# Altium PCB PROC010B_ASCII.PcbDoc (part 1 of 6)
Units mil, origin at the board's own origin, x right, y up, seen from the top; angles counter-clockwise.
Board outline 3180 x 2565 mil, 6 copper layers (TOP, L2, L3, L4, L5, BOTTOM), stack 55.54 mil thick; 362 components, 264 nets, 1248 pads, 1144 vias.
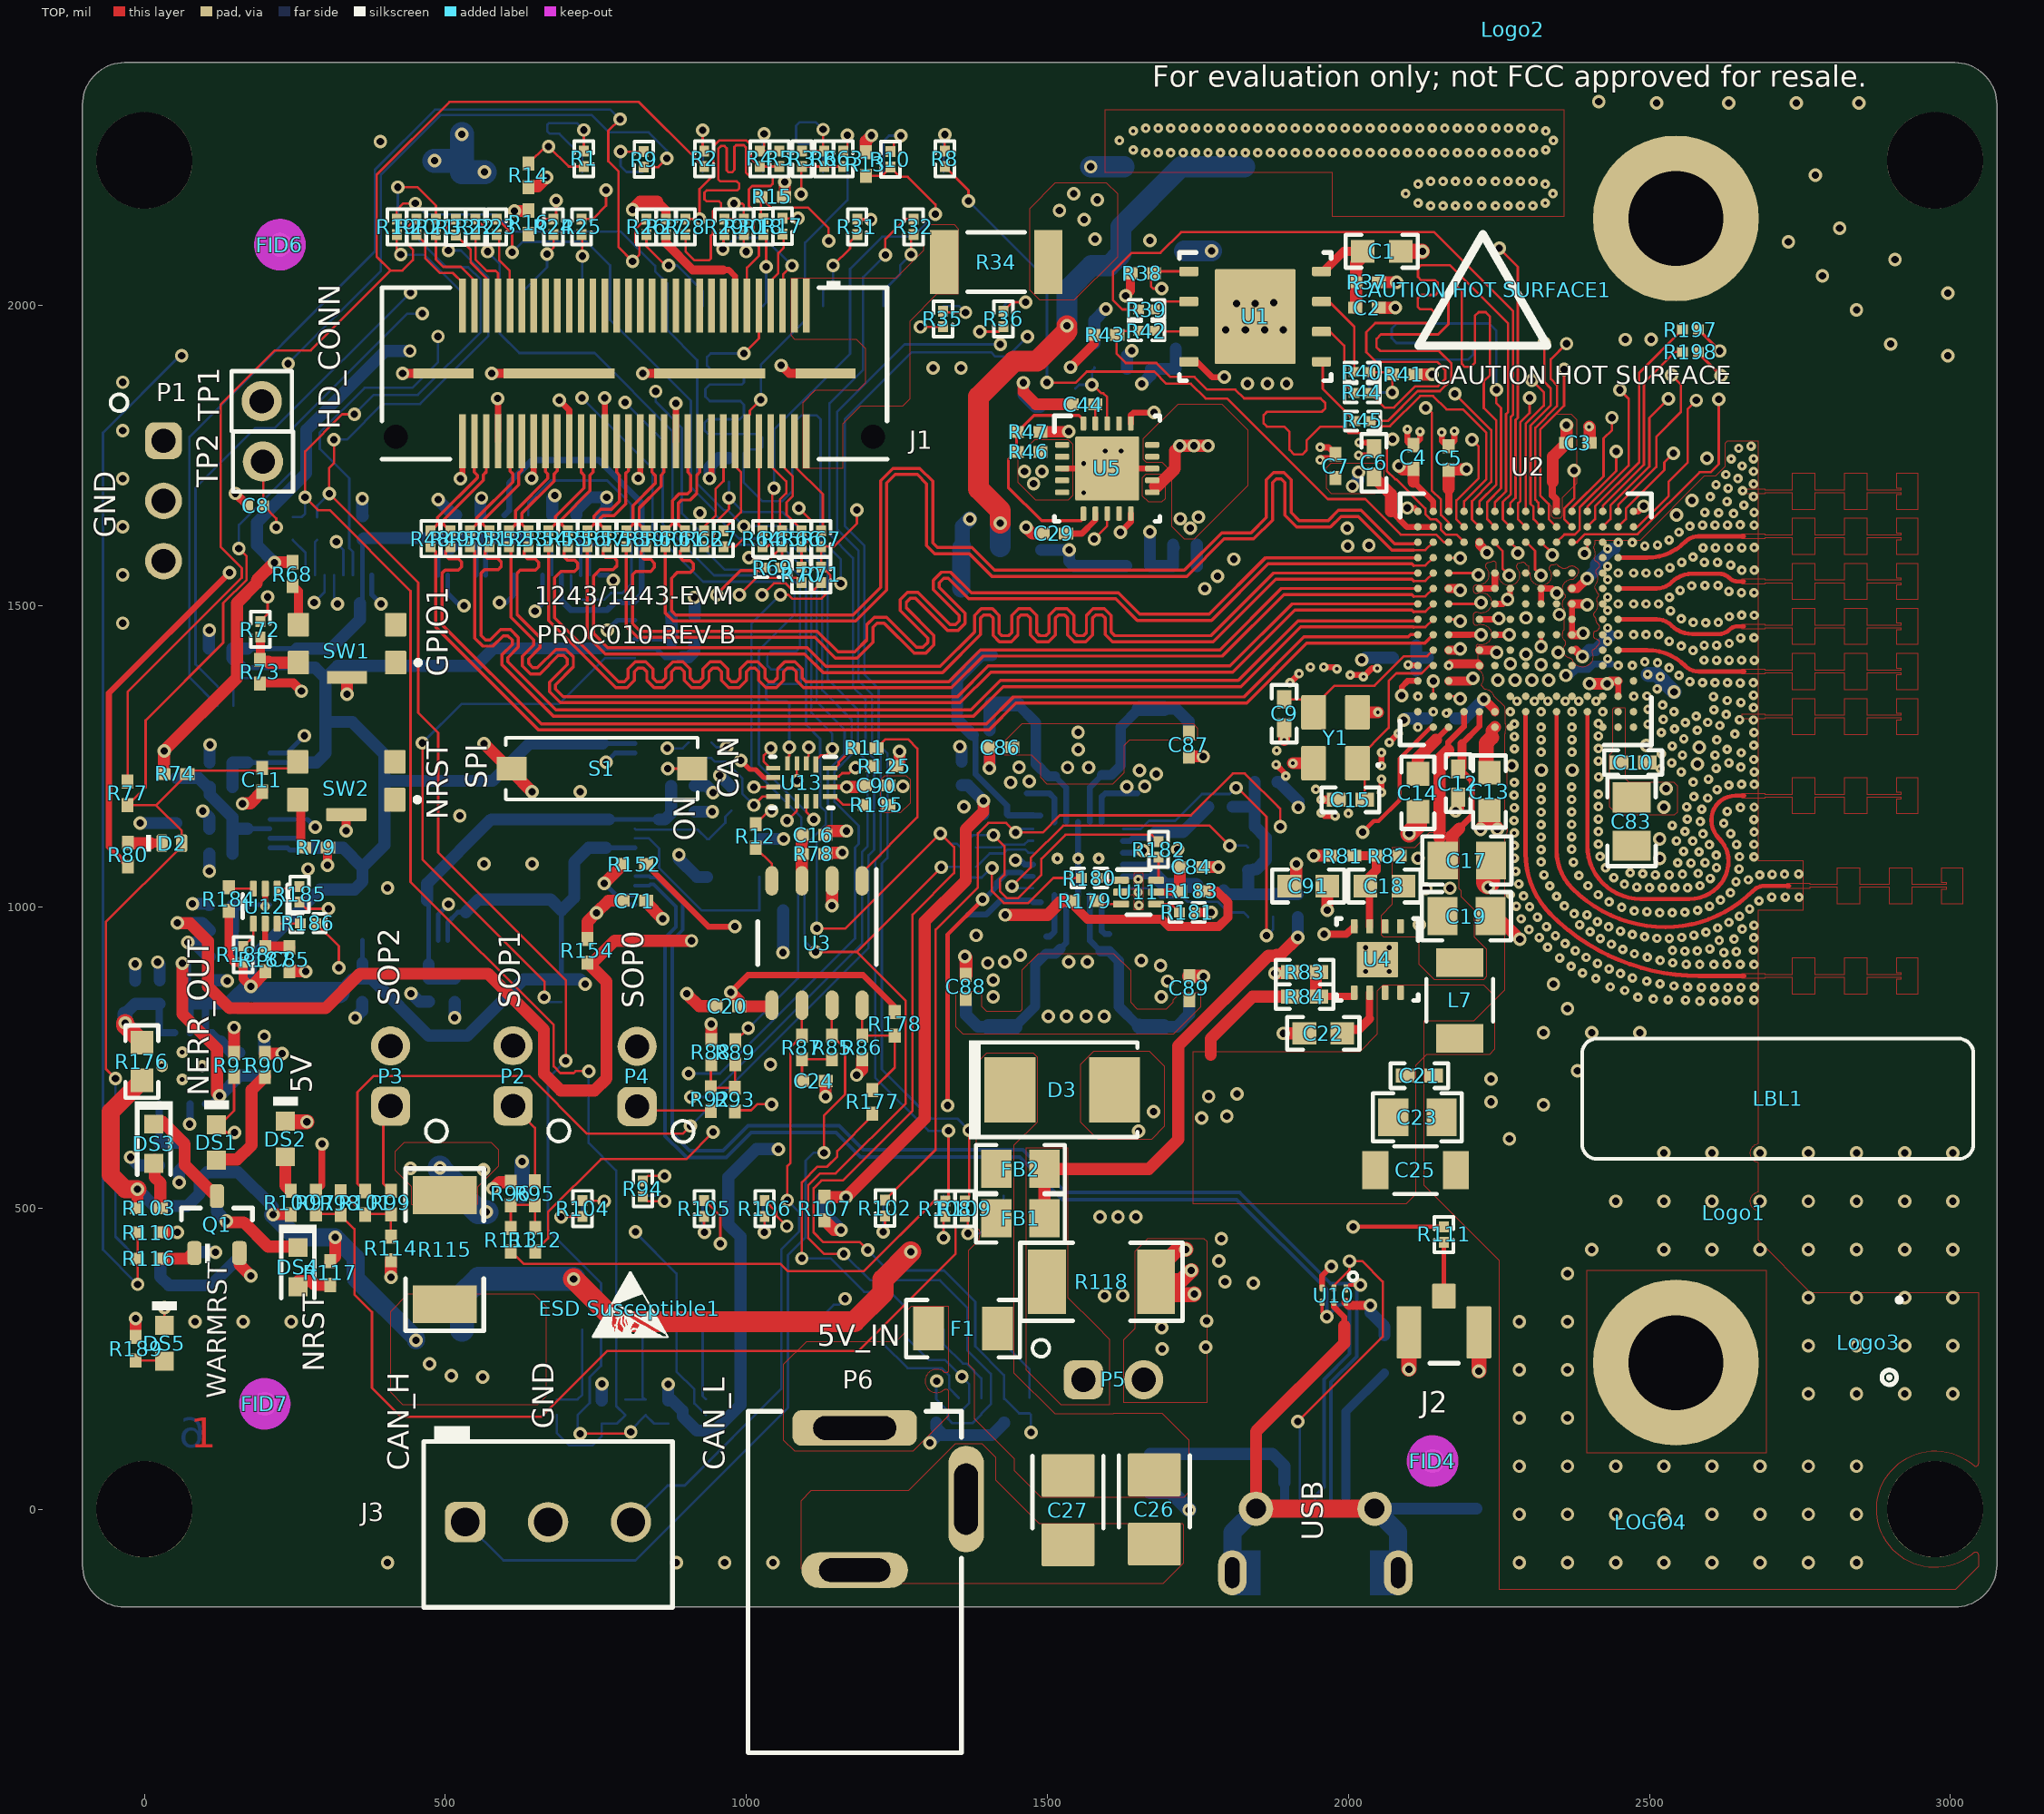
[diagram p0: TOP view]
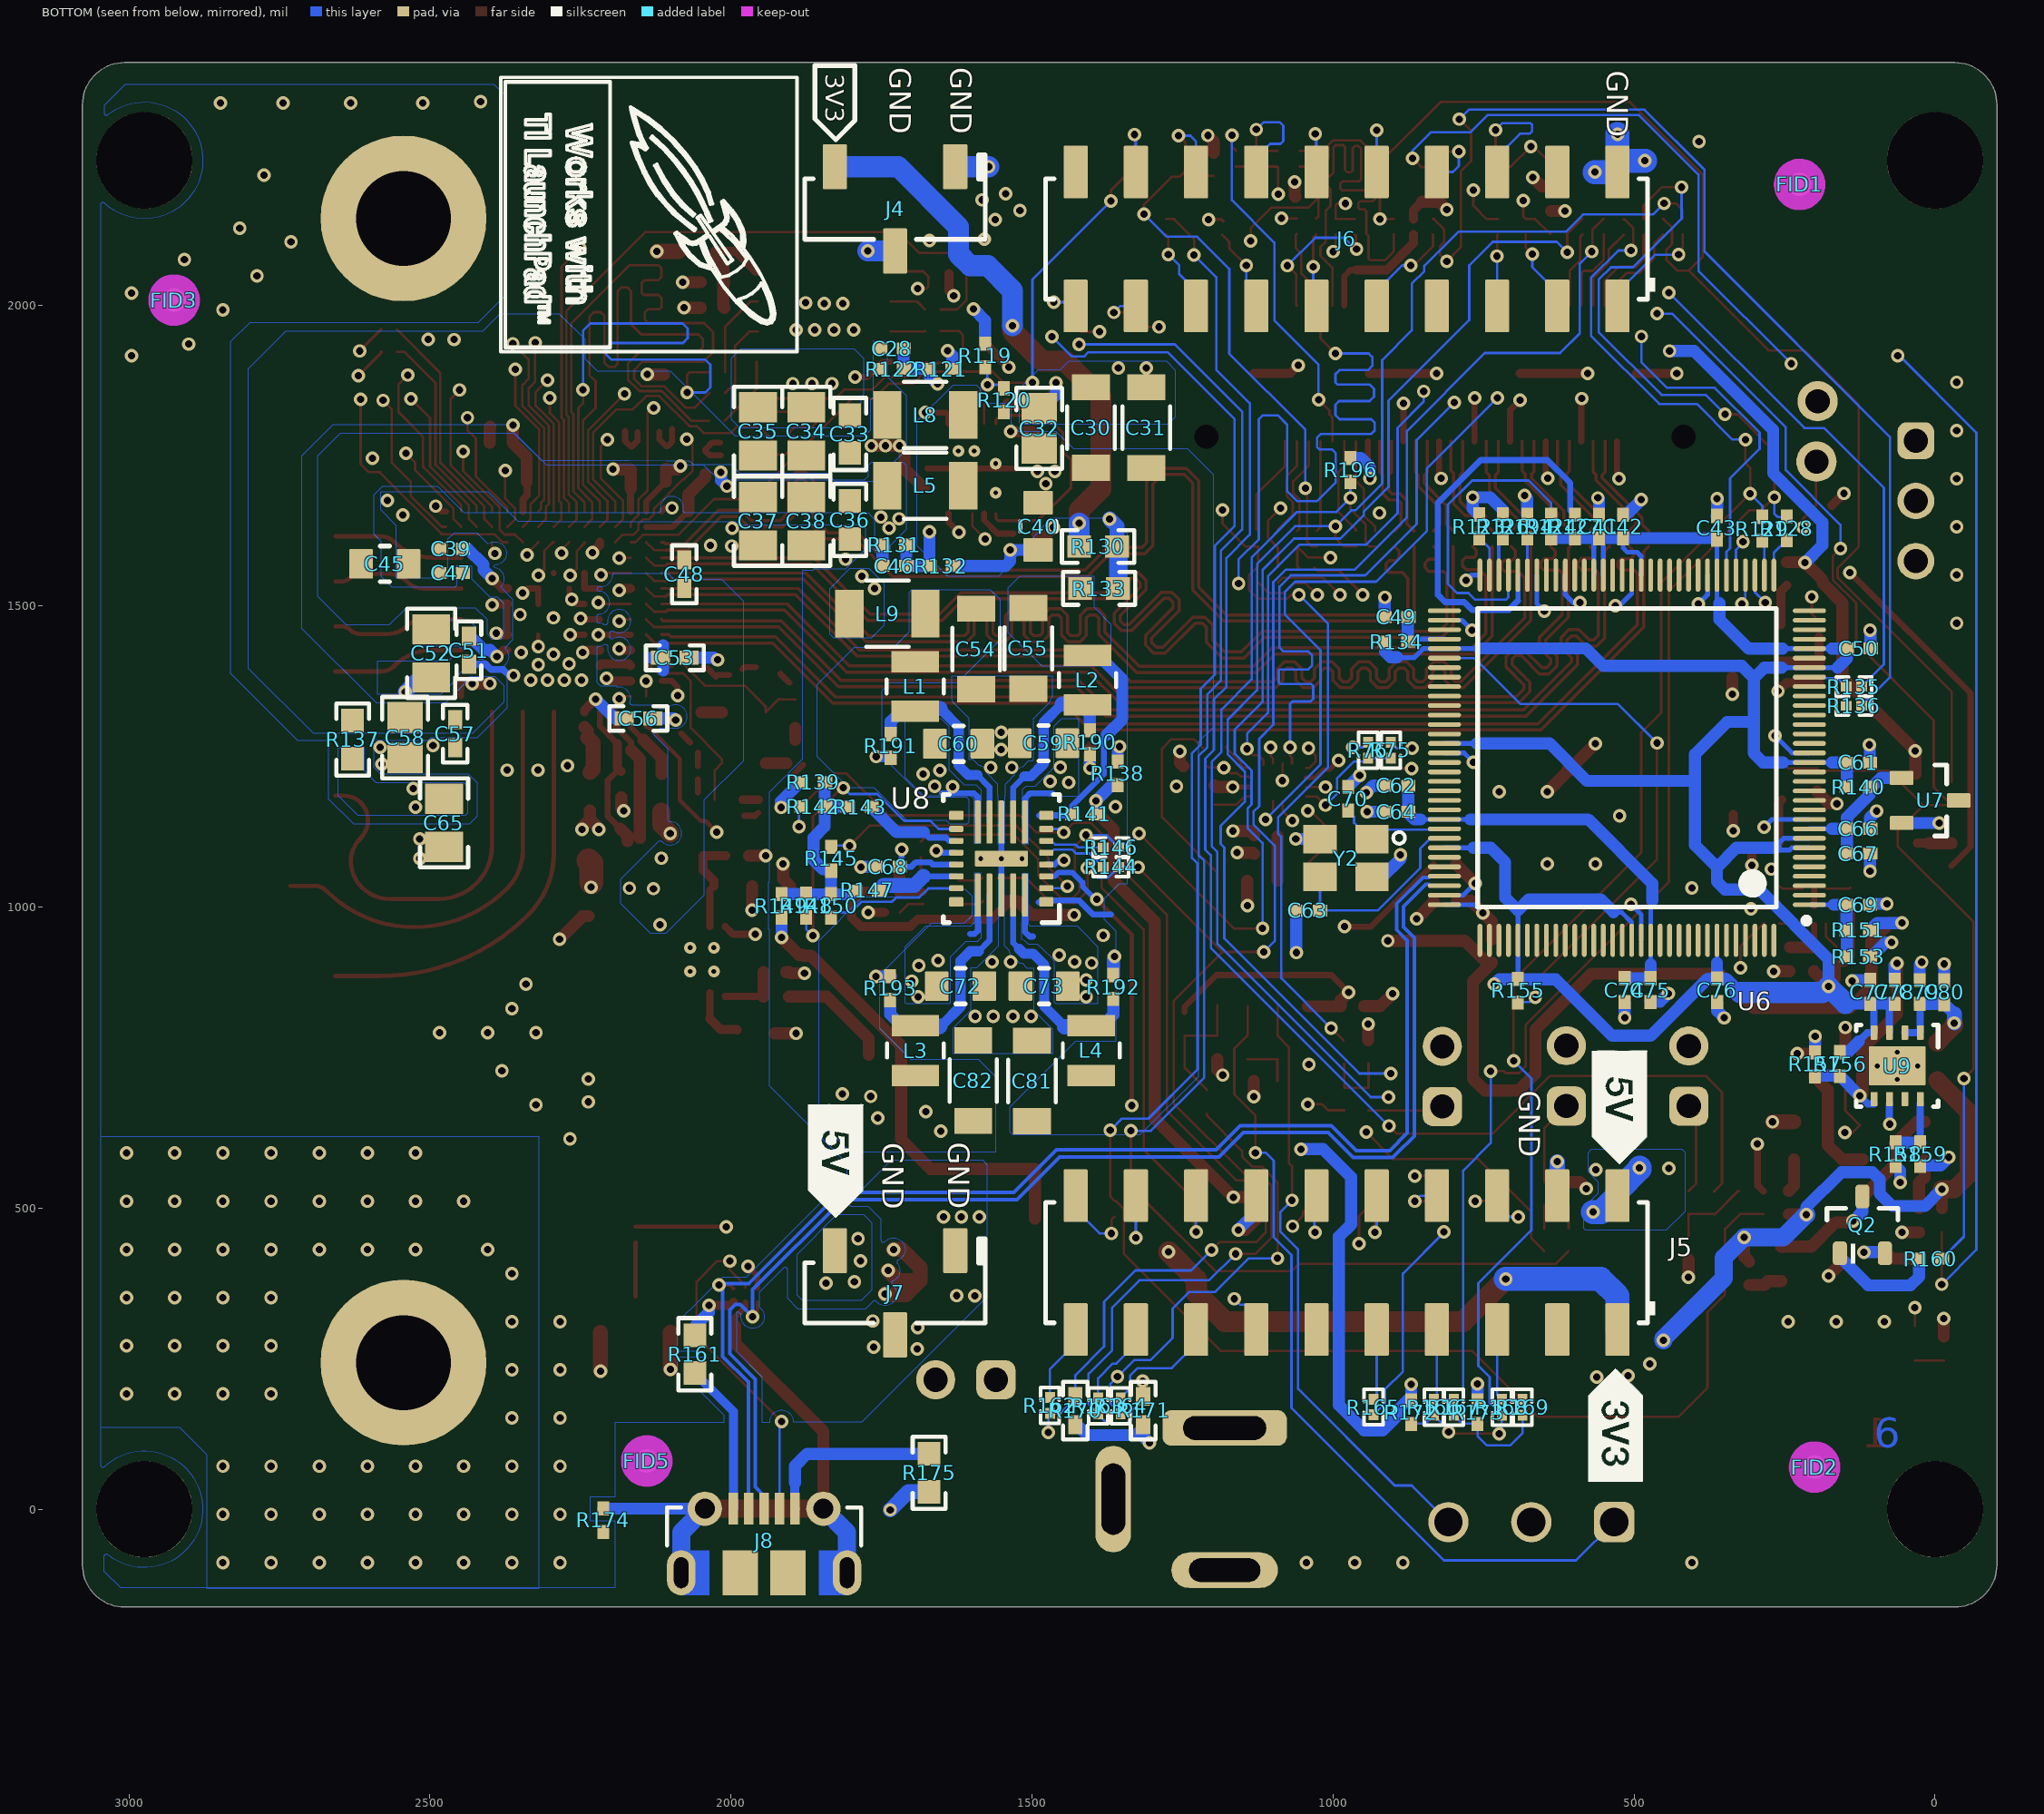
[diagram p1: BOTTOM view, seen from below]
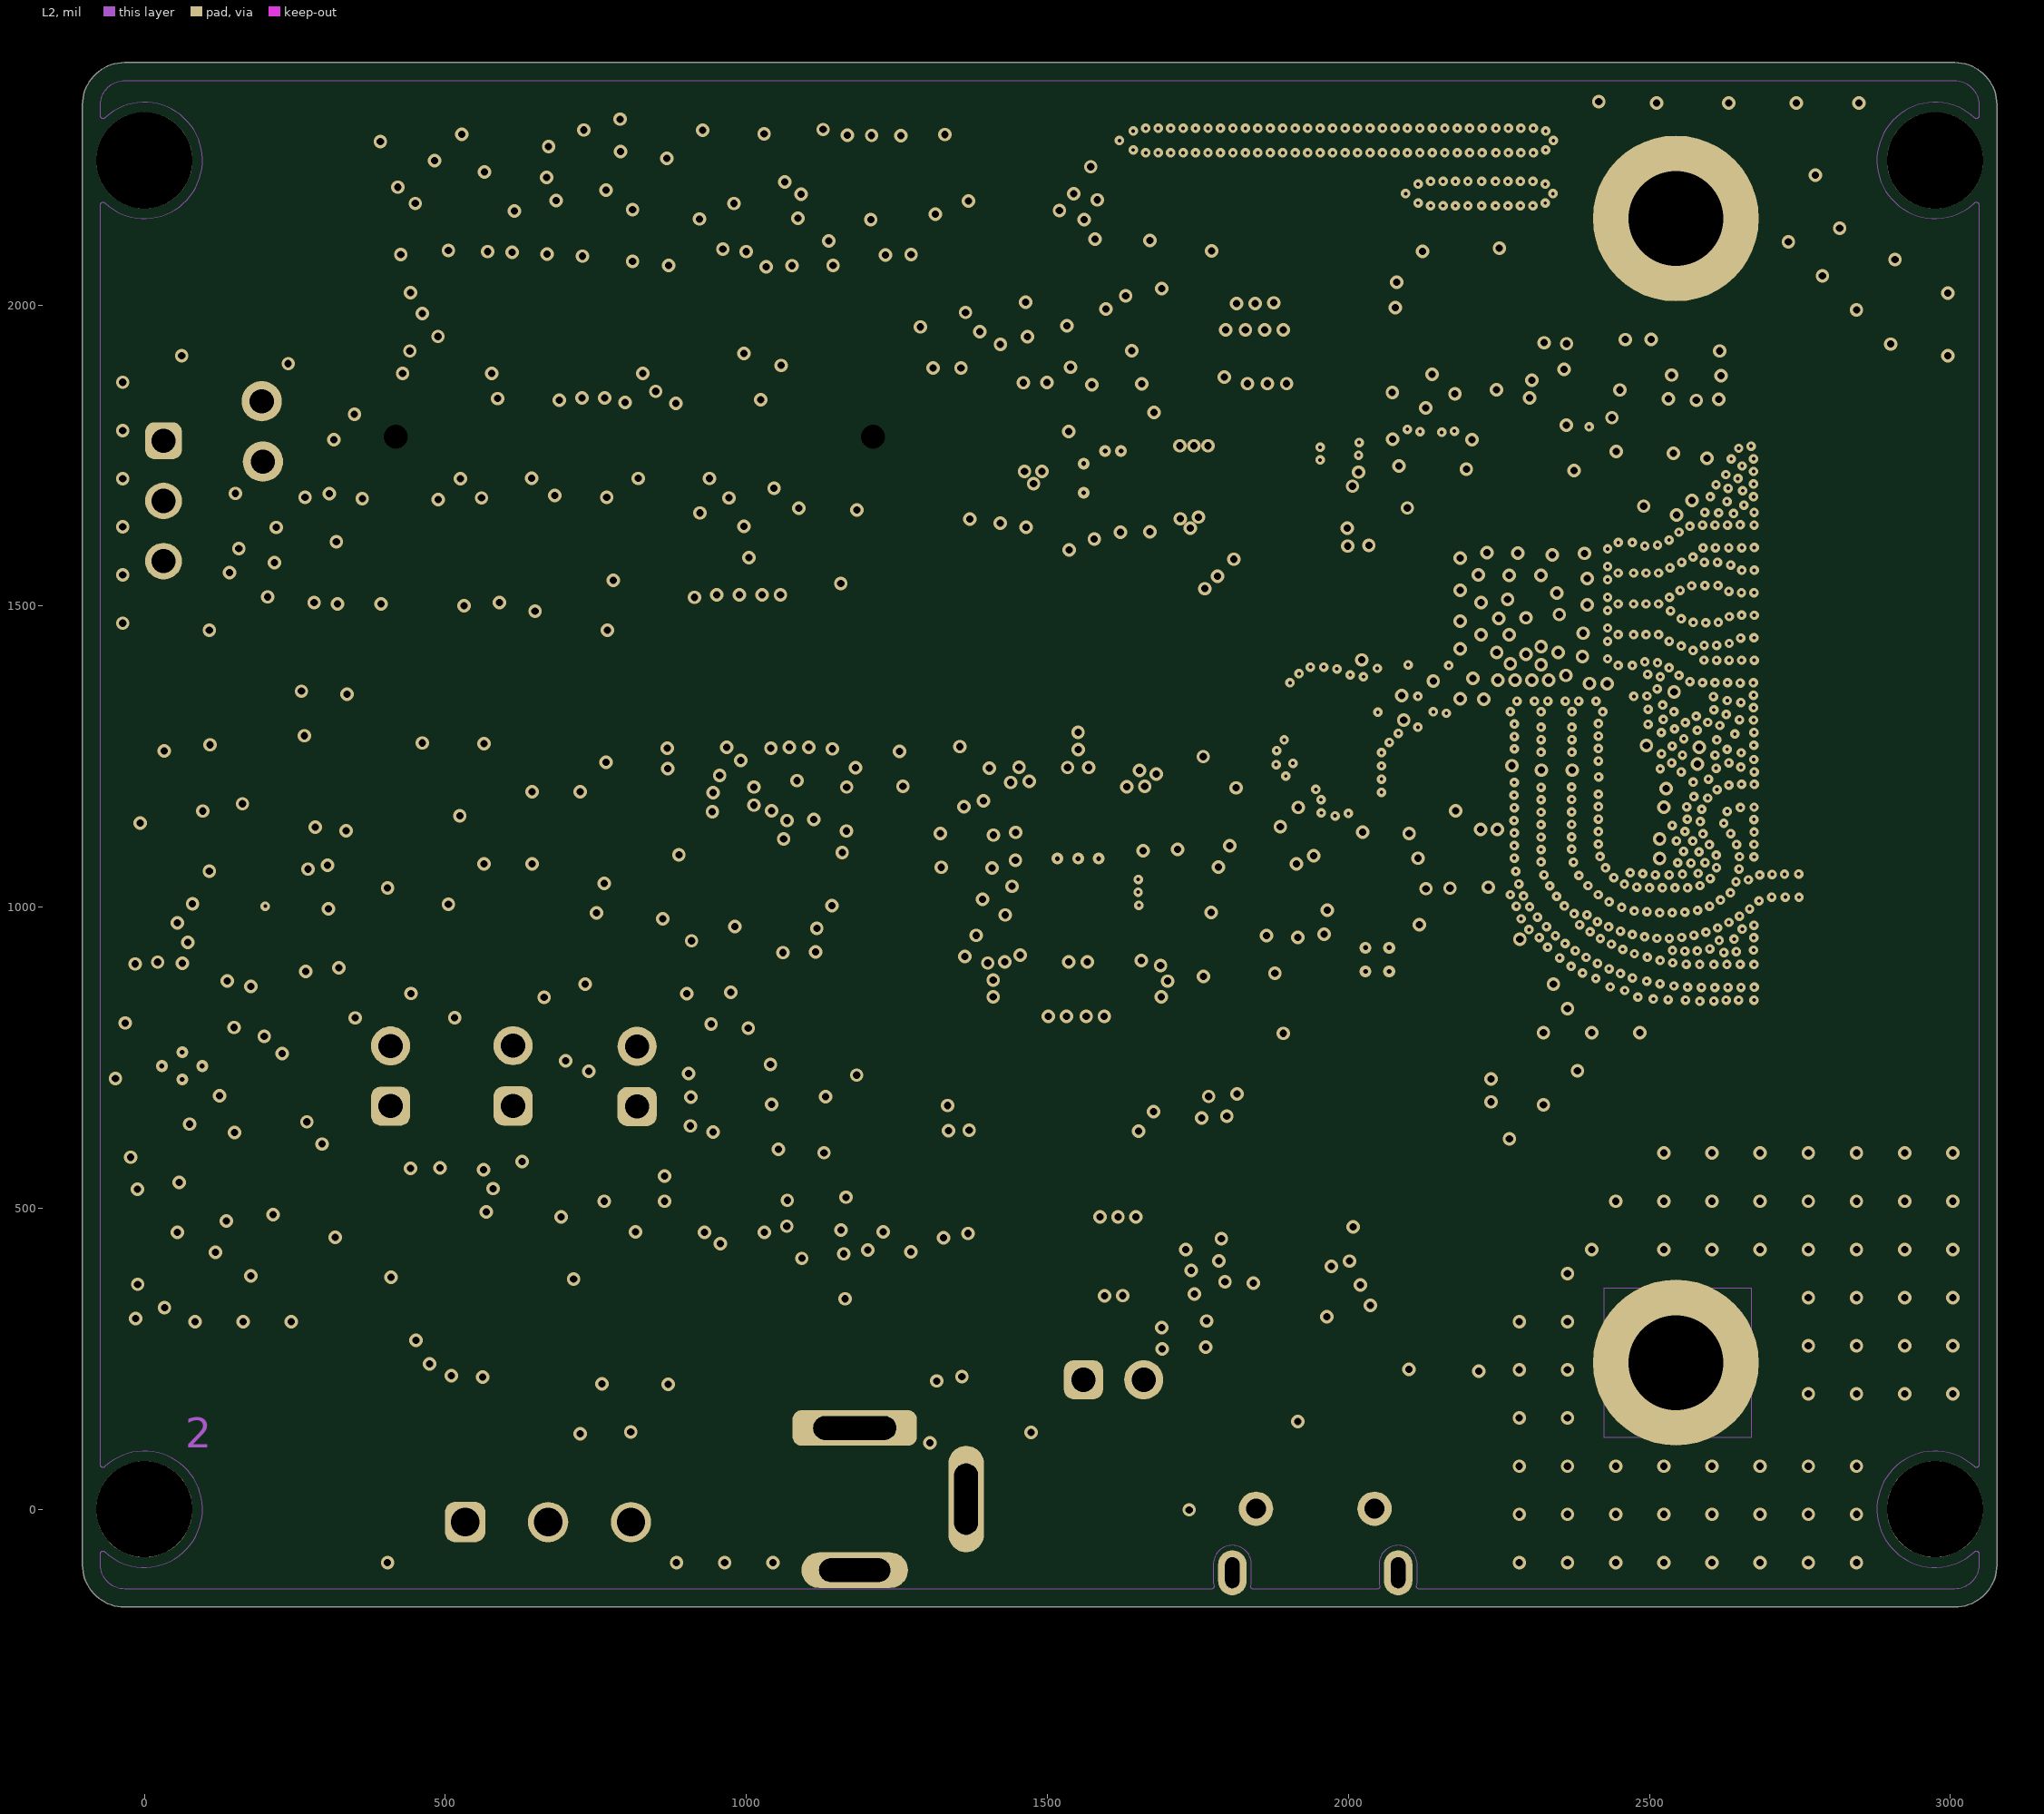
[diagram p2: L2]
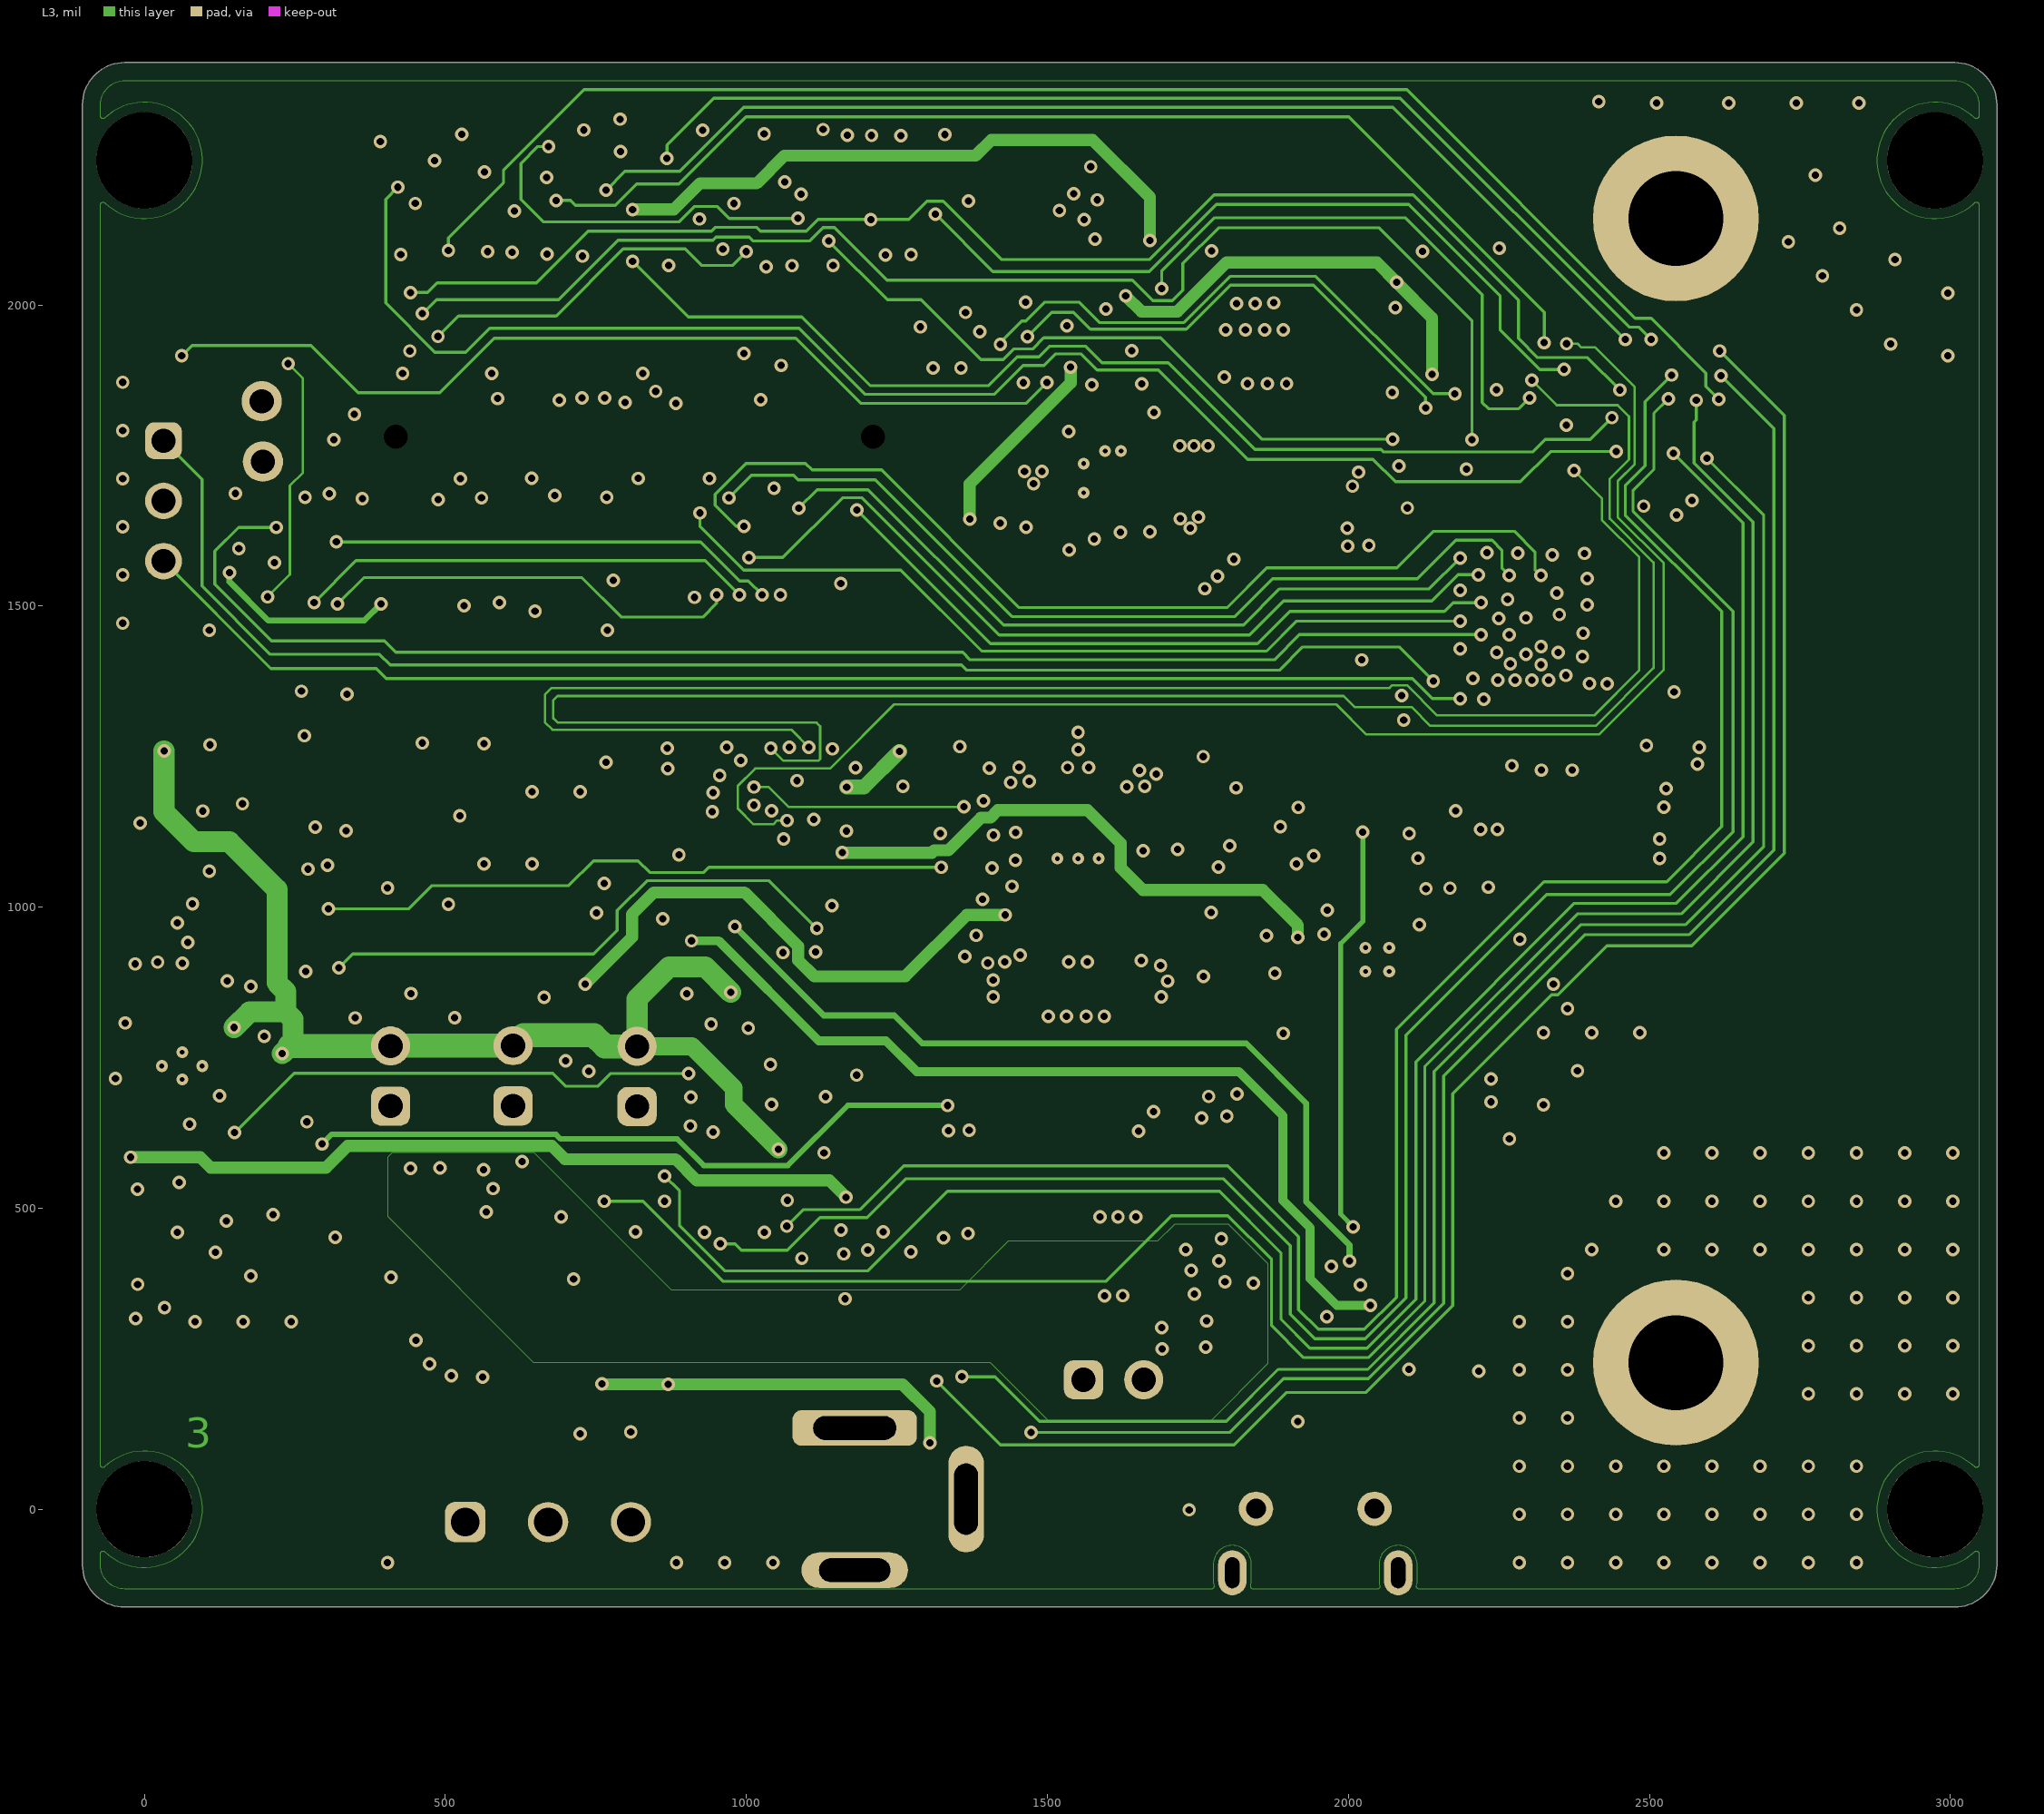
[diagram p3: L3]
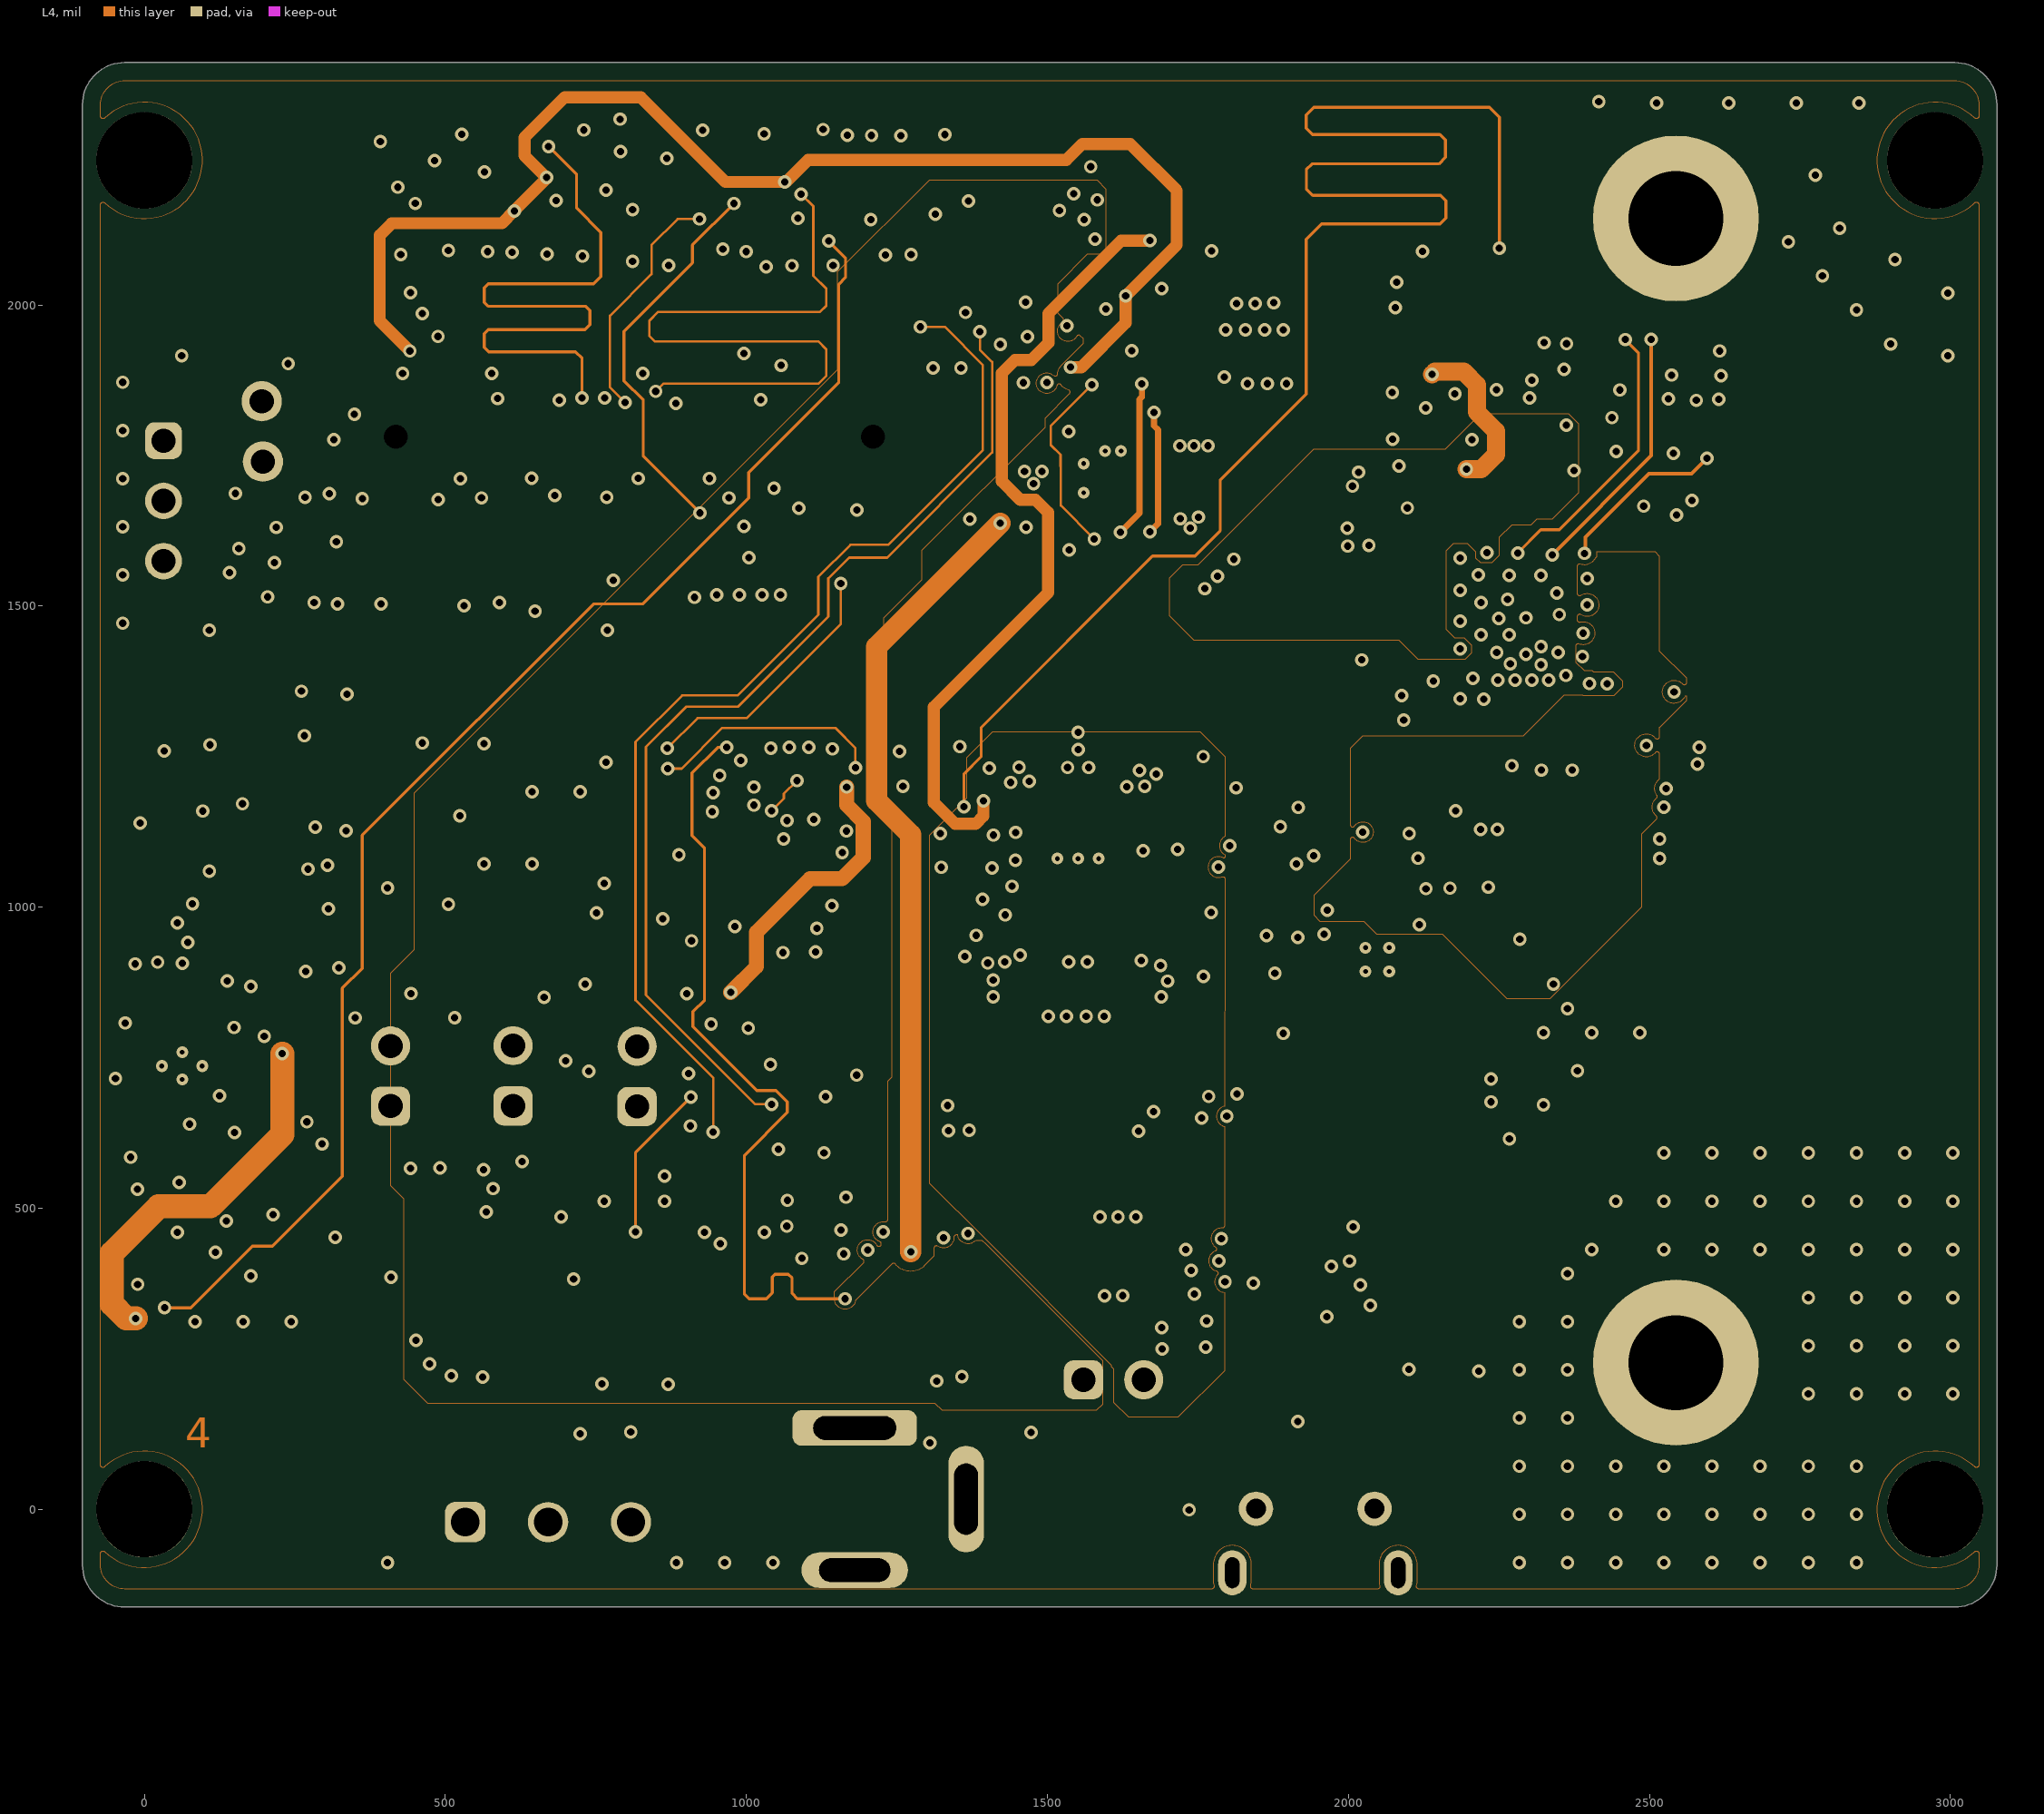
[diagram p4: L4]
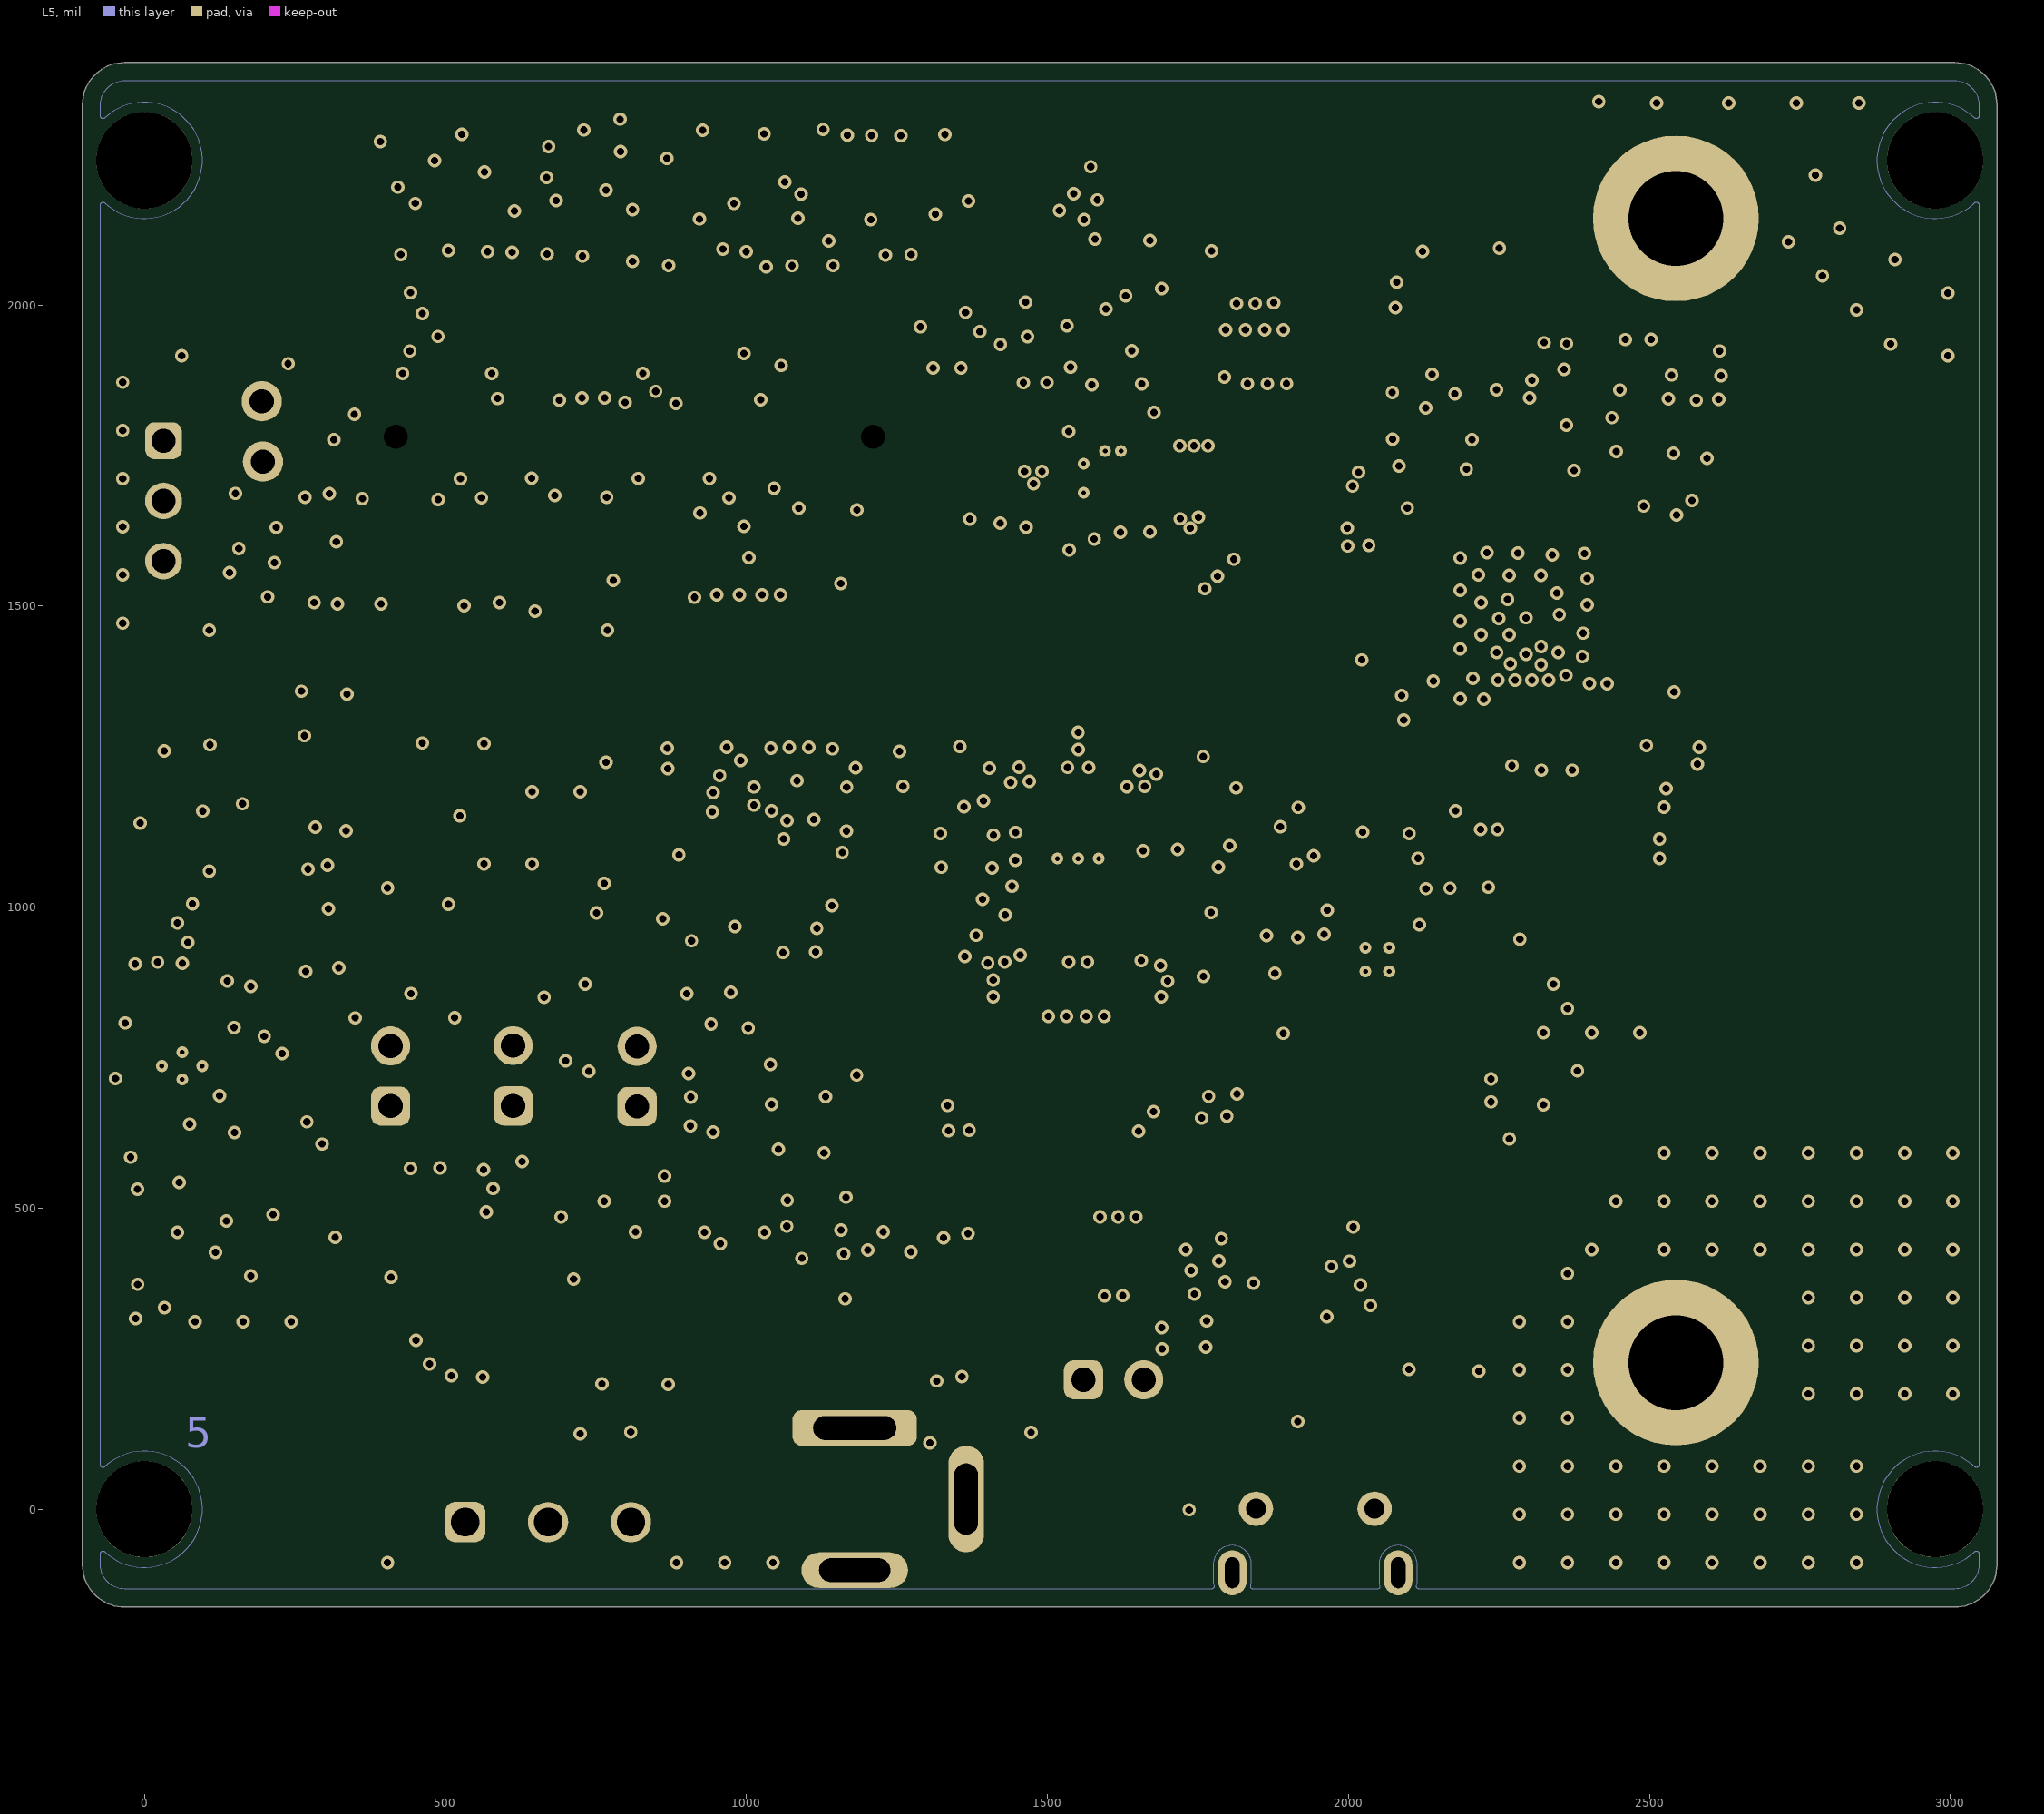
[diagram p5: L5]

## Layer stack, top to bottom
Top Solder: solder mask 0.8, Solder Resist, Dk 3.5
TOP: signal copper 1.6
Dielectric 1: core 4, RO4835 LOPRO, Dk 3.66
L2: signal copper 1.2
Dielectric2: core 2.85, FR4 370HR, Dk 3.9
Dielectric 3: dielectric 2.85, FR4 370HR, Dk 3.9
L3: signal copper 1.2
Dielectric4: core 28, FR4 370HR, Dk 4.36
L4: signal copper 1.2
Dielectric5: core 2.92, FR4 370HR, Dk 3.9
Dielectric 6: dielectric 2.92, FR4 370HR, Dk 3.9
L5: signal copper 1.2
Dielectric7: core 4, FR4 370HR, Dk 4.26
BOTTOM: signal copper 1.6
Bottom Solder: solder mask 0.8, Solder Resist, Dk 3.5

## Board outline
-32.75,-162.5 cw(c-32.75,-92.5) -102.75,-92.5 -102.75,2332.5 cw(c-32.75,2332.5) -32.75,2402.5 3007.25,2402.5 cw(c3007.25,2332.5) 3077.25,2332.5 3077.25,-92.5 cw(c3007.25,-92.5) 3007.25,-162.5

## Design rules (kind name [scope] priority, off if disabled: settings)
AssemblyTestPointUsage [All] p0: scope1count=1 scope1_0_kind=Board scope1_0_value=Board scope2count=1 scope2_0_kind=Board scope2_0_value=Board commentlength=0
AssemblyTestpoint [All] p0: scope1count=1 scope1_0_kind=Board scope1_0_value=Board scope2count=1 scope2_0_kind=Board scope2_0_value=Board commentlength=0
Clearance Clearance_RF [All] p0 off: scope1count=1 scope1_0_kind=Board scope1_0_value=Board scope2count=1 scope2_0_kind=Board scope2_0_value=Board commentlength=45 gap=6.73 // Protel DXP Scope 2 Expression Was: inpoly
Clearance Clearance_L34 [All] p0 off: scope1count=1 scope1_0_kind=Board scope1_0_value=Board scope2count=1 scope2_0_kind=Board scope2_0_value=Board commentlength=60 gap=15 // Protel DXP Scope 1 Expression Was: InLayerClass('L3_L4')
Clearance Clearance_PMIC [All] p0 off: scope1count=1 scope1_0_kind=Board scope1_0_value=Board scope2count=1 scope2_0_kind=Board scope2_0_value=Board commentlength=70 gap=5 // Protel DXP Scope 1 Expression Was: WithinRoom('Copper to PMIC IC')
Clearance Clearance_BTM [All] p0: scope1count=1 scope1_0_kind=Layer scope1_0_value=BOTTOM scope2count=1 scope2_0_kind=Board scope2_0_value=Board commentlength=0 gap=15
Clearance Clearance_L25 [All] p0 off: scope1count=1 scope1_0_kind=Board scope1_0_value=Board scope2count=1 scope2_0_kind=Board scope2_0_value=Board commentlength=60 gap=15 // Protel DXP Scope 1 Expression Was: InLayerClass('L2_L5')
Clearance RX_TX_L34 [All] p0 off: scope1count=1 scope1_0_kind=Board scope1_0_value=Board scope2count=1 scope2_0_kind=NetClass scope2_0_value=RX_TX commentlength=60 gap=10 // Protel DXP Scope 1 Expression Was: InLayerClass('L3_L4')
Clearance COPLANNER [All] p0 off: scope1count=1 scope1_0_kind=Board scope1_0_value=Board scope2count=1 scope2_0_kind=Board scope2_0_value=Board commentlength=81 gap=3 // Protel DXP Scope 1 Expression Was: WithinRoom('COUPLE') and not OnLayer('L4')
Clearance Clearance_1 [All] p0 off: scope1count=1 scope1_0_kind=Board scope1_0_value=Board scope2count=1 scope2_0_kind=Board scope2_0_value=Board commentlength=69 gap=6.71 // Protel DXP Scope 1 Expression Was: WithinRoom('DUT') OR InPolygon
Clearance Clearance_TOP [All] p0: scope1count=1 scope1_0_kind=Layer scope1_0_value=TOP scope2count=1 scope2_0_kind=Board scope2_0_value=Board commentlength=0 gap=10
Clearance RX_TX_L25 [All] p0 off: scope1count=1 scope1_0_kind=Board scope1_0_value=Board scope2count=1 scope2_0_kind=NetClass scope2_0_value=RX_TX commentlength=60 gap=10 // Protel DXP Scope 1 Expression Was: InLayerClass('L2_L5')
Clearance RX_TX_TOP [All] p0: scope1count=1 scope1_0_kind=Layer scope1_0_value=TOP scope2count=1 scope2_0_kind=NetClass scope2_0_value=RX_TX commentlength=0 gap=10
Clearance same_net_cl_inner [All] p0 off: scope1count=1 scope1_0_kind=Board scope1_0_value=Board scope2count=1 scope2_0_kind=Board scope2_0_value=Board commentlength=61 gap=10 // Protel DXP Scope 1 Expression Was: InLayerClass('layers')
Clearance Clearance_RF [InNetClass('RF') and not ispad vs inpoly] p1: gap=6.73 ignorepadtopadclearanceinfootprint=FALSE
Clearance Clearance_L34 [InLayerClass('L3_L4')] p2: gap=15 ignorepadtopadclearanceinfootprint=FALSE except(0: Arc-Hole Track-Hole SMDPad-Hole THPad-Hole Via-Hole Fill-Hole Poly-Hole Region-Hole Text-Hole; 5: Arc-Track Arc-SMDPad Track-Track Track-SMDPad; 5.9: Via-Via; 6: Arc-Arc Arc-THPad Arc-Via Track-THPad Track-Via SMDPad-SMDPad SMDPad-THPad SMDPad-Via SMDPad-Fill SMDPad-Poly THPad-THPad THPad-Via Via-Fill Via-Poly; 10: THPad-Fill THPad-Poly)
Clearance Clearance_PMIC [WithinRoom('Copper to PMIC IC')] p3: gap=5 ignorepadtopadclearanceinfootprint=FALSE except(0: Arc-Hole Track-Hole SMDPad-Hole THPad-Hole Via-Hole Fill-Hole Poly-Hole Region-Hole Text-Hole; 4: Arc-Track Track-Track; 4.5: Track-Via SMDPad-SMDPad)
Clearance Clearance_BTM [OnLayer('BOTTOM')] p4: gap=15 ignorepadtopadclearanceinfootprint=FALSE except(0: Arc-SMDPad Arc-Hole Track-Hole SMDPad-Hole THPad-Hole Via-Hole Fill-Hole Poly-Hole Region-Hole Text-Hole; 4: Track-SMDPad; 4.5: Arc-Via Track-Via; 5: Arc-Arc Arc-Track Track-Track SMDPad-Via; 6: Arc-THPad Track-THPad SMDPad-SMDPad SMDPad-THPad THPad-THPad THPad-Via; 8: Arc-Fill Arc-Poly Track-Fill Track-Poly Via-Fill Via-Poly; 9: SMDPad-Fill SMDPad-Poly THPad-Fill THPad-Poly; 16.6: Via-Via)
Clearance Clearance_L25 [InLayerClass('L2_L5')] p5: gap=15 ignorepadtopadclearanceinfootprint=FALSE except(0: Arc-Hole Track-Hole SMDPad-Hole THPad-Hole Via-Hole Fill-Hole Poly-Hole Region-Hole Text-Hole; 5: Arc-Track Arc-SMDPad Track-Track Track-SMDPad; 6: Arc-Arc Arc-THPad Arc-Via Track-THPad Track-Via SMDPad-SMDPad SMDPad-THPad SMDPad-Via SMDPad-Fill SMDPad-Poly THPad-THPad THPad-Via Via-Via Via-Fill Via-Poly; 10: THPad-Fill THPad-Poly)
Clearance RX_TX_L34 [InLayerClass('L3_L4') vs InNetClass('RX_TX')] p6: gap=10 ignorepadtopadclearanceinfootprint=FALSE except(0: Arc-Hole Track-Hole SMDPad-Hole THPad-Hole Via-Hole Fill-Hole Poly-Hole Region-Hole Text-Hole; 4.86: Via-Via; 5: Arc-SMDPad Track-SMDPad; 6: Arc-Arc Arc-Track Arc-THPad Arc-Via Track-Track Track-THPad Track-Via SMDPad-SMDPad SMDPad-THPad SMDPad-Via SMDPad-Fill SMDPad-Poly THPad-THPad THPad-Via Via-Fill Via-Poly; 15: Arc-Fill Arc-Poly Track-Poly Fill-Fill Fill-Poly Poly-Poly; 16: Track-Fill)
Clearance COPLANNER [WithinRoom('COUPLE') and not OnLayer('L4')] p7: gap=3 ignorepadtopadclearanceinfootprint=FALSE except(0: Arc-Hole Track-Hole SMDPad-Hole THPad-Hole Via-Hole Fill-Hole Poly-Hole Region-Hole Text-Hole)
Clearance Clearance_1 [WithinRoom('DUT') OR InPolygon] p8: gap=6.71 ignorepadtopadclearanceinfootprint=FALSE except(0: Arc-Hole Track-Hole SMDPad-Hole THPad-Hole Via-Hole Fill-Hole Poly-Hole Region-Hole Text-Hole; 4: Track-Track Track-SMDPad Track-Via SMDPad-Via; 6.6: Via-Region; 6.72: Arc-Region Arc-Text Track-Region Track-Text SMDPad-Region SMDPad-Text THPad-Region THPad-Text Via-Text Fill-Region Fill-Text Poly-Region Poly-Text Region-Region Region-Text Text-Text; 9: SMDPad-Poly; 10: THPad-Poly)
Clearance Clearance_TOP [OnLayer('TOP')] p9: gap=10 ignorepadtopadclearanceinfootprint=FALSE except(0: Arc-SMDPad Arc-Hole Track-Hole SMDPad-Hole THPad-Hole Via-Hole Fill-Hole Poly-Hole Region-Hole Text-Hole; 4: Arc-Arc Arc-Track Arc-Via Track-Track Track-Via; 5: Track-SMDPad SMDPad-Via; 6: Arc-THPad Track-THPad SMDPad-SMDPad SMDPad-THPad THPad-THPad THPad-Via Via-Fill Via-Poly; 8: Arc-Fill Arc-Poly Track-Fill Track-Poly; 9: SMDPad-Fill SMDPad-Poly THPad-Fill THPad-Poly; 15: Fill-Fill Fill-Poly Poly-Poly; 15.4: Via-Via)
Clearance RX_TX_L25 [InLayerClass('L2_L5') vs InNetClass('RX_TX')] p10: gap=10 ignorepadtopadclearanceinfootprint=FALSE except(0: Arc-Hole Track-Hole SMDPad-Hole THPad-Hole Via-Hole Fill-Hole Poly-Hole Region-Hole Text-Hole; 5: Arc-SMDPad Track-SMDPad; 6: Arc-Arc Arc-Track Arc-THPad Arc-Via Track-Track Track-THPad Track-Via SMDPad-SMDPad SMDPad-THPad SMDPad-Via SMDPad-Fill SMDPad-Poly THPad-THPad THPad-Via Via-Fill Via-Poly; 9.1: Via-Via; 15: Arc-Fill Arc-Poly Track-Fill Track-Poly Fill-Fill Fill-Poly Poly-Poly)
Clearance RX_TX_TOP [OnLayer('TOP') vs InNetClass('RX_TX')] p11: gap=10 ignorepadtopadclearanceinfootprint=FALSE except(0: Arc-Hole Track-Hole SMDPad-Hole THPad-Hole Via-Hole Fill-Hole Poly-Hole Region-Hole Text-Hole; 4: Arc-Track Arc-SMDPad Track-Track Track-SMDPad SMDPad-Via; 6: Arc-THPad Track-THPad SMDPad-SMDPad SMDPad-THPad THPad-THPad THPad-Via THPad-Fill THPad-Poly; 6.7: Arc-Fill Arc-Poly Track-Fill Track-Poly; 6.72: Arc-Via Track-Via Via-Fill Via-Poly; 9: SMDPad-Fill SMDPad-Poly; 15.4: Via-Via)
Clearance same_net_cl_inner [InLayerClass('layers')] p12: gap=10 ignorepadtopadclearanceinfootprint=FALSE except(0: Arc-Hole Track-Hole SMDPad-Hole THPad-Hole Via-Hole Fill-Hole Poly-Hole Region-Hole Text-Hole; 5: Arc-THPad Track-Track Track-SMDPad Track-THPad SMDPad-SMDPad SMDPad-THPad THPad-THPad; 6: Track-Via SMDPad-Via THPad-Via Via-Via Via-Fill Via-Poly; 15: Arc-Fill Arc-Poly Fill-Fill Fill-Poly Poly-Poly)
ComponentClearance [All] p0: scope1count=1 scope1_0_kind=Board scope1_0_value=Board scope2count=1 scope2_0_kind=Board scope2_0_value=Board commentlength=0 gap=-1 collisioncheckmode=3
ComponentClearance [All] p1: gap=-1 collisioncheckmode=3 verticalgap=2 showdistances=FALSE
DiffPairsRouting DiffPairsRouting_LVDS [All] p0: scope1count=1 scope1_0_kind=NetClass scope1_0_value=LVDS scope2count=1 scope2_0_kind=Board scope2_0_value=Board commentlength=0
DiffPairsRouting DiffPairsRouting_USB [All] p0: scope1count=1 scope1_0_kind=NetClass scope1_0_value=USB scope2count=1 scope2_0_kind=Board scope2_0_value=Board commentlength=0
DiffPairsRouting DiffPairsRouting_USB [InNetClass('USB')] p1: maxlimit=5.6 minlimit=5.6 mostfreqgap=5.6 toplayer_minwidth=6 toplayer_maxwidth=6 toplayer_prefwidth=6 midlayer1_minwidth=6 midlayer1_maxwidth=6 midlayer1_prefwidth=6 midlayer2_minwidth=6 midlayer2_maxwidth=6 midlayer2_prefwidth=6 midlayer3_minwidth=6 midlayer3_maxwidth=6 midlayer3_prefwidth=6 midlayer4_minwidth=6 midlayer4_maxwidth=6 midlayer4_prefwidth=6 bottomlayer_minwidth=6 bottomlayer_maxwidth=6 bottomlayer_prefwidth=6 maxuncoupledlength=500
DiffPairsRouting DiffPairsRouting_LVDS [InNetClass('LVDS')] p2: maxlimit=5 minlimit=5 mostfreqgap=5 toplayer_minwidth=4 toplayer_maxwidth=5.2 toplayer_prefwidth=5.2 midlayer1_minwidth=4 midlayer1_maxwidth=5.2 midlayer1_prefwidth=5.2 midlayer2_minwidth=4 midlayer2_maxwidth=5.2 midlayer2_prefwidth=5.2 midlayer3_minwidth=4 midlayer3_maxwidth=5.2 midlayer3_prefwidth=5.2 midlayer4_minwidth=4 midlayer4_maxwidth=5.2 midlayer4_prefwidth=5.2 bottomlayer_minwidth=4 bottomlayer_maxwidth=5.2 bottomlayer_prefwidth=5.2 maxuncoupledlength=500
FabricationTestPointUsage [All] p0: scope1count=1 scope1_0_kind=Board scope1_0_value=Board scope2count=1 scope2_0_kind=Board scope2_0_value=Board commentlength=0 valid=0 allowmultiple=FALSE
FabricationTestpoint [All] p0: scope1count=1 scope1_0_kind=Board scope1_0_value=Board scope2count=1 scope2_0_kind=Board scope2_0_value=Board commentlength=0 side=3 testpointundercomponent=TRUE minsize=40 maxsize=100 preferedsize=60 minholesize=0 maxholesize=40 preferedholesize=32 testpointgrid=1
FanoutControl Fanout_Default [All] p0: scope1count=1 scope1_0_kind=Board scope1_0_value=Board scope2count=1 scope2_0_kind=Board scope2_0_value=Board commentlength=30 // Fanout_Default (Default Rule)
FanoutControl Fanout_Small [All] p0 off: scope1count=1 scope1_0_kind=Board scope1_0_value=Board scope2count=1 scope2_0_kind=Board scope2_0_value=Board commentlength=84 // Protel DXP Scope 1 Expression Was: (CompPinCount < 5)   Fanout_Small (Default Rule)
FanoutControl Fanout_SOIC [All] p0 off: scope1count=1 scope1_0_kind=Board scope1_0_value=Board scope2count=1 scope2_0_kind=Board scope2_0_value=Board commentlength=71 // Protel DXP Scope 1 Expression Was: IsSOIC   Fanout_SOIC (Default Rule)
FanoutControl Fanout_LCC [All] p0 off: scope1count=1 scope1_0_kind=Board scope1_0_value=Board scope2count=1 scope2_0_kind=Board scope2_0_value=Board commentlength=69 // Protel DXP Scope 1 Expression Was: IsLCC   Fanout_LCC (Default Rule)
FanoutControl Fanout_BGA [All] p0 off: scope1count=1 scope1_0_kind=Board scope1_0_value=Board scope2count=1 scope2_0_kind=Board scope2_0_value=Board commentlength=69 // Protel DXP Scope 1 Expression Was: IsBGA   Fanout_BGA (Default Rule)
Height [All] p0: scope1count=1 scope1_0_kind=Board scope1_0_value=Board scope2count=1 scope2_0_kind=Board scope2_0_value=Board commentlength=0
HoleSize [All] p0: scope1count=1 scope1_0_kind=Board scope1_0_value=Board scope2count=1 scope2_0_kind=Board scope2_0_value=Board commentlength=0 absolutevalues=TRUE maxlimit=200 minlimit=5.9 maxpercent=80.000 minpercent=20.000
HoleSize [All] p1: absolutevalues=TRUE maxlimit=200 minlimit=5.9 maxpercent=80.000 minpercent=20.000
HoleToHoleClearance [All] p0: scope1count=1 scope1_0_kind=Board scope1_0_value=Board scope2count=1 scope2_0_kind=Board scope2_0_value=Board commentlength=0
LayerPairs [All] p0: scope1count=1 scope1_0_kind=Board scope1_0_value=Board scope2count=1 scope2_0_kind=Board scope2_0_value=Board commentlength=0 enforce=TRUE
MinimumAnnularRing [All] p0: scope1count=1 scope1_0_kind=Board scope1_0_value=Board scope2count=1 scope2_0_kind=Board scope2_0_value=Board commentlength=0 minimumring=3
MinimumAnnularRing [All] p1: minimumring=3
MinimumSolderMaskSliver [All] p0: scope1count=1 scope1_0_kind=Board scope1_0_value=Board scope2count=1 scope2_0_kind=Board scope2_0_value=Board commentlength=0
MinimumSolderMaskSliver [All] p1: minsoldermaskwidth=2
NetAntennae [All] p0: scope1count=1 scope1_0_kind=Board scope1_0_value=Board scope2count=1 scope2_0_kind=Board scope2_0_value=Board commentlength=0
PasteMaskExpansion [All] p0: scope1count=1 scope1_0_kind=Board scope1_0_value=Board scope2count=1 scope2_0_kind=Board scope2_0_value=Board commentlength=0 expansion=0
PlaneClearance [All] p0: scope1count=1 scope1_0_kind=Board scope1_0_value=Board scope2count=1 scope2_0_kind=Board scope2_0_value=Board commentlength=0 clearance=20
PlaneConnect [All] p0: scope1count=1 scope1_0_kind=Board scope1_0_value=Board scope2count=1 scope2_0_kind=Board scope2_0_value=Board commentlength=0 planeconnectstyle=Direct reliefexpansion=20 reliefentries=4 reliefconductorwidth=10 reliefairgap=10
PlaneConnect [All] p1: planeconnectstyle=Direct reliefexpansion=20 reliefentries=4 reliefconductorwidth=10 reliefairgap=10
PolygonConnect [All] p0: scope1count=1 scope1_0_kind=Board scope1_0_value=Board scope2count=1 scope2_0_kind=Board scope2_0_value=Board commentlength=0 connectstyle=Direct reliefconductorwidth=10 reliefentries=4 polygonreliefangle="90 Angle"
PolygonConnect [All] p1: connectstyle=Direct reliefconductorwidth=10 reliefentries=4 polygonreliefangle="90 Angle" airgapwidth=10
RoomDefinition COUPLE [All] p0 off: scope1count=1 scope1_0_kind=Board scope1_0_value=Board scope2count=1 scope2_0_kind=Board scope2_0_value=Board commentlength=63 region_x1=33703740 region_y1=42686220 region_x2=41573760 region_y2=44618700 confinementstyle=ConfineOut // Protel DXP Scope 1 Expression Was: WithinRoom('CO_PLANNER')
RoomDefinition DUT [All] p0: scope1count=1 scope1_0_kind=ComponentClass scope1_0_value=DUT scope2count=1 scope2_0_kind=Board scope2_0_value=Board commentlength=0 region_x1=38441690 region_y1=29482510 region_x2=48386870 region_y2=38673070 confinementstyle=ConfineIn
RoomDefinition "Copper to PMIC IC" [All] p0: scope1count=1 scope1_0_kind=Board scope1_0_value=Board scope2count=1 scope2_0_kind=Board scope2_0_value=Board commentlength=0 region_x1=32135000 region_y1=30482250 region_x2=34784410 region_y2=33656490 confinementstyle=ConfineIn
RoomDefinition "Copper to PMIC IC" [All] p1: confinementstyle=ConfineIn formatcopy=TRUE lockcomponents=FALSE outline 1421.5,1231.65 1686.44,1231.65 1686.44,914.22 1421.5,914.22
RoomDefinition DUT [InComponentClass('DUT')] p2: confinementstyle=ConfineIn formatcopy=TRUE lockcomponents=FALSE outline 3046.69,814.25 2272.5,814.25 2228.68,858.9 2228.68,1299.21 2052.17,1299.21 2052.17,1299.2 2052.17,1733.31 3043.03,1733.31
RoomDefinition COUPLE [WithinRoom('CO_PLANNER')] p3: confinementstyle=ConfineOut formatcopy=TRUE lockcomponents=FALSE outline 1578.38,2327.87 1578.38,2213.88 1578.37,2213.87 1968.78,2213.87 1968.78,2134.62 2365.38,2134.62 2365.38,2327.86 1578.37,2327.86
RoutingCorners [All] p0: scope1count=1 scope1_0_kind=Board scope1_0_value=Board scope2count=1 scope2_0_kind=Board scope2_0_value=Board commentlength=0 cornerstyle=45-Degree minsetback=100 maxsetback=100
RoutingLayers [All] p0: scope1count=1 scope1_0_kind=Board scope1_0_value=Board scope2count=1 scope2_0_kind=Board scope2_0_value=Board commentlength=0 top layer=Automatic mid layer 1=Automatic mid layer 2=Automatic mid layer 3=Automatic mid layer 4=Automatic bottom layer=Automatic
RoutingPriority [All] p0: scope1count=1 scope1_0_kind=Board scope1_0_value=Board scope2count=1 scope2_0_kind=Board scope2_0_value=Board commentlength=0
RoutingTopology [All] p0: scope1count=1 scope1_0_kind=Board scope1_0_value=Board scope2count=1 scope2_0_kind=Board scope2_0_value=Board commentlength=0 topology=Shortest
RoutingVias [All] p0: scope1count=1 scope1_0_kind=Board scope1_0_value=Board scope2count=1 scope2_0_kind=Board scope2_0_value=Board commentlength=0 holewidth=28 width=50 viastyle="Through Hole" minholewidth=5 minwidth=15 maxholewidth=28 maxwidth=50
RoutingVias [All] p1: holewidth=28 width=50 viastyle="Through Hole" minholewidth=5 minwidth=15 maxholewidth=28 maxwidth=50
ShortCircuit [All] p0: scope1count=1 scope1_0_kind=Board scope1_0_value=Board scope2count=1 scope2_0_kind=Board scope2_0_value=Board commentlength=0 allowed=FALSE
SilkToBoardRegionClearance [All] p0 off: scope1count=1 scope1_0_kind=Board scope1_0_value=Board scope2count=1 scope2_0_kind=Board scope2_0_value=Board commentlength=130 // Protel DXP Scope 1 Expression Was: Not ((IsComment or IsDesignator) And (Hide <> 'False')) and not InRegion(1000,500,4000,800)
SilkToBoardRegionClearance [Not ((IsComment or IsDesignator) And (Hide <> 'False')) and not InRegion(1000,500,4000,800)] p1:
SilkToSilkClearance [All] p0: scope1count=1 scope1_0_kind=Board scope1_0_value=Board scope2count=1 scope2_0_kind=Board scope2_0_value=Board commentlength=0
SilkToSilkClearance [All] p1: silktosilkclearance=3
SilkToSolderMaskClearance [All] p0 off: scope1count=1 scope1_0_kind=Board scope1_0_value=Board scope2count=1 scope2_0_kind=Board scope2_0_value=Board commentlength=44 // Protel DXP Scope 1 Expression Was: IsPad
SilkToSolderMaskClearance [IsPad] p1: minsilkscreentomaskgap=3 clearancetoexposedcopper=TRUE
SolderMaskExpansion [All] p0: scope1count=1 scope1_0_kind=Board scope1_0_value=Board scope2count=1 scope2_0_kind=Board scope2_0_value=Board commentlength=0 expansion=0
SolderMaskExpansion [All] p1: expansion=0
UnRoutedNet [All] p0: scope1count=1 scope1_0_kind=Board scope1_0_value=Board scope2count=1 scope2_0_kind=Board scope2_0_value=Board commentlength=0
UnpouredPolygon [All] p0: scope1count=1 scope1_0_kind=Board scope1_0_value=Board scope2count=1 scope2_0_kind=Board scope2_0_value=Board commentlength=0
Width [All] p0: scope1count=1 scope1_0_kind=Board scope1_0_value=Board scope2count=1 scope2_0_kind=Board scope2_0_value=Board commentlength=0 maxlimit=100 minlimit=4 preferedwidth=10
Width [All] p1: maxlimit=100 minlimit=4 preferedwidth=10
22 further rules are at their usual default settings.

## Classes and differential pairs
net class USB: XDSET_1_D_N XDSET_1_D_P
net class Undefined: NetR128_2
net class SPI: AR_CS1 AR_HOSTINTR1 AR_MISO1 AR_MOSI1 AR_SPICLK1 CS1 D_LOGGER MISO1 MOSI1 NetJ1_7 NetJ1_9 NetJ1_10 NetJ1_11 NetJ1_12 NetJ5_13 NetJ6_12 NetJ6_14 NetJ6_16 SPICLK1
net class RF: RX1 RX2 RX3 RX4 TX1 TX2 TX3
net class QSPI: AR_QSPI_CS AR_QSPI_D0 AR_QSPI_D1 AR_QSPI_D2 AR_QSPI_D3 AR_QSPI_SCLK NetR39_2 NetR40_1 NetR42_2 NetR44_1 NetR45_1
net class PWR: 3V3_BRD 3V3_MON_XDS_1 5V_IN 5V_UNREG +3.3VD AR_1P3_RF1 AR_1P3_RF2 AR_1V2 AR_1V4_APLL AR_1V4_SYNTH AR_1V8 AR_VBGAP AR_VOUT_PA GND MCU_3V3 MCU_5V NetC1_2 NetC18_2 NetC26_1 NetC28_1 NetC46_1 NetC78_1 NetC79_2 NetF1_2 PGOOD PMIC_1V0 PMIC_1V2 PMIC_1V8 PMICOUT_3V3 PMICVIO_3V3 VDDC_1 XDSET_1_VBUS XDSET_VBAT XDSET_VREFA
net class LVDS: AR_LVDS_VALID_N AR_LVDS_VALID_P AR_LVDSCSI0_N AR_LVDSCSI0_P AR_LVDSCSI1_N AR_LVDSCSI1_P AR_LVDSCSI2_N AR_LVDSCSI2_P AR_LVDSCSI3_N AR_LVDSCSI3_P AR_LVDSCSI_CLK_N AR_LVDSCSI_CLK_P AR_LVDSCSI_FRCLK_N AR_LVDSCSI_FRCLK_P HD_LVDS_VALID_N HD_LVDS_VALID_P HD_LVDSCSI0_N HD_LVDSCSI0_P HD_LVDSCSI1_N HD_LVDSCSI1_P HD_LVDSCSI2_N HD_LVDSCSI2_P HD_LVDSCSI3_N HD_LVDSCSI3_P HD_LVDSCSI_CLK_N HD_LVDSCSI_CLK_P HD_LVDSCSI_FRCLK_N HD_LVDSCSI_FRCLK_P
net class JTAG: AR_TCK AR_TDI AR_TDO_SOP0 AR_TMS NetJ1_4 NetJ1_5 NetJ1_6 NetJ1_8 XDSET_TCK XDSET_TDI XDSET_TDO XDSET_TMS
net class GENERAL: AR_ANAMUX AR_ANATEST1 AR_ANATEST2 AR_ANATEST3 AR_ANATEST4 AR_BSS_LOGGER AR_GPIO_0 AR_GPIO_1 AR_GPIO_2 AR_MSS_LOGGER AR_NERR_OUT AR_NERRIN AR_NRST AR_RS232RX AR_RS232TX AR_SCL AR_SDA AR_SYNC_IN AR_SYNC_OUT_SOP1 AR_VSENSE AR_WARMRST LDO_01_EN LDO_02_EN MCU_SOP0 MCU_SOP1 MCU_SOP2 NetC22_1 NetC71_2 NetC86_2 NetC87_2 NetC88_2 NetC89_2 NetD2_1 NetDS1_1 NetDS2_1 NetDS3_1 NetDS3_2 NetDS4_1 NetDS4_2 NetDS5_1 NetJ1_13 NetJ1_14 NetJ1_16 NetJ5_6 NetJ5_8 NetJ5_9 NetJ5_10 NetJ5_12 NetJ5_14 NetJ5_15 NetJ5_16 NetJ5_18 NetJ5_19 NetJ6_1 NetJ6_3 NetJ6_8 NetJ6_9 NetJ6_10 NetJ6_11 NetJ6_13 NetJ6_15 NetJ6_17 NetJ6_18 NetJ6_19 NetQ1_1 NetQ2_1 NetR68_1 NetR72_1 NetR79_2 NetR86_1 NetR88_2 NetR95_1 NetR98_2 NetR123_1 NetR124_1 NetR126_1 NetR127_1 NetR129_2 NetR143_1 NetR144_2 NetR146_1 NetR147_1 NetR152_1 NetR194_2 NetR197_2 NetR198_2 PGOOD PMIC_EN1 PMIC_EN2 PMIC_EN3 PMIC_NRST SS_CTRL SW0 SW1 SW2 SW3 VBUS_1_DETECT XDSET_1_ID XDSET_LOGGER XDSET_NRST
net class CLK: AR_MCUCLKOUT AR_OSC_CLKOUT AR_PMIC_CLKOUT_SOP2 AR_XTALM AR_XTALP NetJ2_1 NetJ5_20 NetJ6_5 PMIC_CLK XDSET_OSC0 XDSET_OSC1
net class CAN: CAN_RX CAN_TX NetC24_2 NetJ3_1 NetJ3_3 NetR11_2 NetR12_2
component class "PROC010B_XDS110 Interface_1B": C49 C63 C66 C67 C70 C71 R123 R124 R126 R127 R128 R129 R134 R135 R136 R140 R152 R154 R155 R194 U6 U7 Y2
component class "PROC010B_XDS110 Interface_1A": C41 C42 C43 C50 C61 C62 C64 C69 C74 C75 C76 C77 C78 C79 C80 J8 R151 R153 R156 R157 R158 R159 R161 R174 R175 R176 U9 U10
component class PROC010B_Tempsensor: C84 C85 R179 R180 R181 R182 R183 R184 R185 R186 R187 R188 U11 U12
component class PROC010B_Decoupling_Caps_Reference: C3 C4 C5 C6 C7 C10 C12 C13 C14 C17 C39 C45 C47 C48 C51 C52 C53 C56 C57 C58 C65 C83
component class PROC010B_QSPI_Flash_Reference: C1 C2 R37 R38 R39 R40 R41 R42 R43 R44 R45 U1
component class PROC010B_Pwr_RST_LEDs: C11 C26 C27 D2 D3 DS1 DS2 DS3 DS4 DS5 F1 FB1 FB2 P5 P6 Q1 Q2 R68 R72 R73 R74 R77 R79 R80 R90 R100 R103 R110 R116 R117 R118 R130 R133 R160 R189 SW1 SW2
component class PROC010B_PMIC_Reference: C54 C55 C59 C60 C68 C72 C73 C81 C82 C86 C87 C88 C89 L1 L2 L3 L4 R138 R139 R141 R142 R143 R144 R145 R146 R147 R148 R149 R150 R190 R191 R192 R193 U8
component class "PROC010B_LP Connector": J4 J5 J6 J7 P1 R1 R2 R3 R4 R5 R6 R8 R9 R10 R18 R19 R24 R25 R26 R31 R32 R35 R36 R76 R94 R102 R104 R105 R106 R107 R108 R109 R115 R162 R163 R164 R165 R166 R167 R168 R169 R172 R173
component class PROC010B_LDO: C18 C21 C22 C23 C25 C28 C29 C30 C31 C32 C35 C37 C40 C44 C46 R46 R47 R81 R82 R83 R84 R119 R120 R121 R122 R131 R132 U4 U5
component class "PROC010B_HD Connector": J1 J2 R7 R17 R20 R21 R22 R23 R27 R28 R29 R30 R33 R34 R48 R49 R50 R51 R52 R53 R54 R55 R56 R57 R58 R59 R60 R61 R62 R63 R64 R65 R66 R67 R69 R70 R71 R75 R111
component class PROC010B_SOP_Headers_Reference: P2 P3 P4 R88 R89 R92 R93 R95 R96 R97 R98 R99 R101 R112 R113 R114
component class "PROC010B_CAN Interface": C16 C20 C24 C90 J3 R11 R12 R78 R85 R86 R87 R125 R177 R178 R195 S1 U3 U13
component class Header: P1 P2 P3 P4 P5
component class Label: LBL1
component class AssemblyNote: ZZ1 ZZ2 ZZ3 ZZ4 ZZ5
component class FiducialMark: FID1 FID2 FID3 FID4 FID5 FID6 FID7
component class PROC010B_Hardware: "CAUTION HOT SURFACE1" "ESD Susceptible1" FID1 FID2 FID3 FID4 FID5 FID6 FID7 LBL1 Logo1 Logo2 Logo3 LOGO4 ZZ1 ZZ2 ZZ3 ZZ4 ZZ5
component class Logo: Logo1
component class PROC010B_DUT_Reference: C8 C9 C15 R13 R14 R15 R16 R91 R170 R171 R196 R197 R198 TP1 TP2 U2 Y1
component class PROC010B_LC_Filtering_Reference: C19 C33 C34 C36 C38 C91 L5 L7 L8 L9 R137
differential pair XDSET_1_D: +XDSET_1_D_P -XDSET_1_D_N
differential pair HD_LVDSCSI_FRCLK: +HD_LVDSCSI_FRCLK_P -HD_LVDSCSI_FRCLK_N
differential pair HD_LVDSCSI_CLK: +HD_LVDSCSI_CLK_P -HD_LVDSCSI_CLK_N
differential pair HD_LVDSCSI3: +HD_LVDSCSI3_P -HD_LVDSCSI3_N
differential pair HD_LVDSCSI2: +HD_LVDSCSI2_P -HD_LVDSCSI2_N
differential pair HD_LVDSCSI1: +HD_LVDSCSI1_P -HD_LVDSCSI1_N
differential pair HD_LVDSCSI0: +HD_LVDSCSI0_P -HD_LVDSCSI0_N
differential pair HD_LVDS_VALID: +HD_LVDS_VALID_P -HD_LVDS_VALID_N
differential pair AR_LVDSCSI_FRCLK: +AR_LVDSCSI_FRCLK_P -AR_LVDSCSI_FRCLK_N
differential pair AR_LVDSCSI_CLK: +AR_LVDSCSI_CLK_P -AR_LVDSCSI_CLK_N
differential pair AR_LVDSCSI3: +AR_LVDSCSI3_P -AR_LVDSCSI3_N
differential pair AR_LVDSCSI2: +AR_LVDSCSI2_P -AR_LVDSCSI2_N
differential pair AR_LVDSCSI1: +AR_LVDSCSI1_P -AR_LVDSCSI1_N
differential pair AR_LVDSCSI0: +AR_LVDSCSI0_P -AR_LVDSCSI0_N
differential pair " ": +AR_LVDS_VALID_P -AR_LVDS_VALID_N

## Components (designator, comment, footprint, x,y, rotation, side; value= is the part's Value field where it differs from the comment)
C1 "GCM188R71C105KA64D" 0603 2055.47,2088.99 r180 top
C2 "CGA2B3X7R1H104K050BB" 0402L 2030.78,1995.26 r180 top
C3 "GCM155R71C224KE02D" 0402L 2381.16,1770.8 r0 top
C4 "GCM155R71C104KA55D" 0402L 2108,1747.43 r90 top
C5 "GCM155R71C224KE02D" 0402L 2166.55,1745.78 r90 top
C6 "GCM155R71C104KA55D" 0402 2042.55,1737.8 r90 top
C7 "GCM155R71C224KE02D" 0402L 1978.55,1732.41 r90 top
C8 "C0603X7S1A104K030BC" 0201_033 184.69,1666.75 r180 top
C9 "GJM1555C1H4R7BB01D" 0402 1893.4,1321.21 r270 top
C10 "GCM155R71C224KE02D" 0402 2473,1240 r0 top
C11 "GCM155R71C104KA55D" 0402L 195.7,1211.25 r90 top
C12 "GCM155R71C224KE02D" 0402 2182.55,1205.8 r270 top
C13 "GCM188R71C105KA64D" 0603 2234.45,1191.9 r270 top
C14 "GCM188R71C105KA64D" 0603 2115.45,1189.8 r270 top
C15 "GJM1555C1H4R7BB01D" 0402 2003.47,1178.2 r0 top
C16 "C0402C104K8RACTU" 0402L 1111.7,1119.67 r180 top
C17 "GCM21BR71A106KE22L" 0805_HV 2196.81,1077.38 r0 top
C18 "GCM188R71C474KA55D" 0603 2059.87,1034.87 r180 top
C19 "GCM21BR71A106KE22L" 0805_HV 2196.23,984.99 r0 top
C20 "C0402C104K8RACTU" 0402L 968.28,835.45 r0 top
C21 "CGA2B3X7R1H104K050BB" 0402 2117.99,720.01 r0 top
C22 "GCM188R71C474KA55D" 0603 1958.47,790.27 r180 top
C23 "GCM21BR71A106KE22L" 0805_HV 2114.63,650.9 r0 top
C24 "C1005X7R1H472K050BA" 0402L 1112.06,711.14 r180 top
C25 "CGA5L1X7R0J226M160AC" 1206_180 2111.8,563.22 r0 top
C26 "T491B476K010AT" 3528-21 1677.7,-0.35 r270 top
C27 "T491B476K010AT" 3528-21 1534.3,-1.55 r270 top
C28 "CGA2B3X8R1H103K050BB" 0402L 1732.83,1927.64 r0 bottom
C29 "CGA2B3X8R1H103K050BB" 0402L 1511.34,1620.25 r0 top
C30 "CGA5L1X7R0J226M160AC" 1206_180 1402,1796.5 r270 bottom
C31 "CGA5L1X7R0J226M160AC" 1206_180 1310.2,1796.25 r270 bottom
C32 "GCM21BR71A106KE22L" 0805 1487.95,1795 r270 bottom
C33 "GCM188R71C105KA64D" 0603 1802.6,1785.62 r270 bottom
C34 "GCM21BR71A106KE22L" 0805_HV 1875,1790 r270 bottom
C35 "GCM21BR71A106KE22L" 0805_HV 1955,1790 r270 bottom
C36 "GCM188R71C105KA64D" 0603 1802.53,1642.85 r90 bottom
C37 "GCM21BR71A106KE22L" 0805_HV 1955,1640.8 r90 bottom
C38 "GCM21BR71A106KE22L" 0805_HV 1875,1640.8 r90 bottom
C39 "GCM155R71C224KE02D" 0402L 2465,1595 r0 bottom
C40 "GCM21BR71A106KE22L" 0805_HV1 1489.95,1632.3 r90 bottom
C41 "C1005X7S0J105M050BC" 0402L 558.3,1631.85 r270 bottom
C42 "C0402C104K8RACTU" 0402L 518.22,1631.85 r270 bottom
C43 "C0402C104K8RACTU" 0402L 362.52,1629.85 r270 bottom
C44 "CGA2B3X8R1H103K050BB" 0402L 1559.98,1834.93 r0 top
C45 "GCM21BR71A106KE22L" 0805_HV1 2575,1570 r180 bottom
C46 "CGA2B3X8R1H103K050BB" 0402L 1728.5,1566.52 r0 bottom
C47 "GCM155R71C224KE02D" 0402L 2465,1555 r0 bottom
C48 "GCM155R71C224KE02D" 0402 2077.55,1552.7 r90 bottom
C49 "C0402C104K8RACTU" 0402L 894.35,1481.9 r180 bottom
C50 "C1005X7R1E103K050BB" 0402L 126.65,1429.4 r0 bottom
C51 "GCM155R71C224KE02D" 0402 2435.27,1426.58 r270 bottom
C52 "GCM21BR71A106KE22L" 0805_HV 2498.15,1421.4 r270 bottom
C53 "GCM155R71C224KE02D" 0402 2093.35,1414 r180 bottom
C54 "GCM31CR71A226KE02" 1206_180 1592.83,1428.59 r90 bottom
C55 "GCM31CR71A226KE02" 1206_180 1506.18,1429.62 r90 bottom
C56 "GCM155R71C224KE02D" 0402 2153.83,1313.3 r180 bottom
C57 "GCM155R71C224KE02D" 0402 2458.2,1287.95 r270 bottom
C58 "GCM21BR71A106KE22L" 0805 2541.18,1281.31 r270 bottom
C59 "GCM21BR71A106KE22L" 0805_HV1 1480.85,1272.15 r180 bottom
C60 "GCM21BR71A106KE22L" 0805_HV1 1621.95,1271.3 r0 bottom
C61 "C1005X7S0J105M050BC" 0402L 127.65,1240.06 r0 bottom
C62 "C1005X7S0J105M050BC" 0402L 894.65,1201.5 r180 bottom
C63 "GRM1555C1H8R0DA01D" 0402L 1041.3,994.36 r180 bottom
C64 "C0402C104K8RACTU" 0402L 894.65,1158.3 r180 bottom
C65 "GCM21BR71A106KE22L" 0805_HV 2476.6,1139.95 r270 bottom
C66 "C0402C103K4RACTU" 0402L 127.19,1130.1 r0 bottom
C67 "C0402C104K8RACTU" 0402L 127.25,1088.8 r0 bottom
C68 "GCM155R71C224KE02D" 0402L 1739.45,1067 r180 bottom
C69 "C0402C103K4RACTU" 0402L 127.65,1003.56 r0 bottom
C70 "GRM1555C1H8R0DA01D" 0402L 975,1179.85 r270 bottom
C71 "C0402C104K8RACTU" 0402L 814,1010.5 r180 top
C72 "GCM21BR71A106KE22L" 0805_HV1 1618.65,868.7 r0 bottom
C73 "GCM21BR71A106KE22L" 0805_HV1 1479.85,868.7 r180 bottom
C74 "C1005X7S1A225K050BC" 0402_065L 515.6,862.15 r90 bottom
C75 "C0402C104K8RACTU" 0402L 472.68,862.15 r90 bottom
C76 "C0402C104K8RACTU" 0402L 361.92,861.85 r90 bottom
C77 "C1005X7S1A225K050BC" 0402_065L 107.82,859.15 r270 bottom
C78 "04025A150FAT2A" 0402L 67.1,859.15 r270 bottom
C79 "C0402C104K8RACTU" 0402L 25.62,858.85 r270 bottom
C80 "C1005X7S1A225K050BC" 0402_065L -15.4,858.5 r270 bottom
C81 "GCM31CR71A226KE02" 1206_180 1499.96,711.43 r270 bottom
C82 "GCM31CR71A226KE02" 1206_180 1597.69,711.75 r270 bottom
C83 "GCM21BR71A106KE22L" 0805_HV 2470.42,1141.98 r270 top
C84 "C0402C104K8RACTU" 0402L 1739.35,1066.5 r180 top
C85 "C0402C104K8RACTU" 0402L 241.11,913.35 r270 top
C86 "CGA2B2NP01H391J050BA" 0402L 1421.7,1265.35 r180 top
C87 "CGA2B2NP01H391J050BA" 0402L 1735,1269.65 r270 top
C88 "CGA2B2NP01H391J050BA" 0402L 1364.7,867.65 r90 top
C89 "CGA2B2NP01H391J050BA" 0402L 1735.6,865.35 r90 top
C90 "C0402C104K8RACTU" 0402L 1216.27,1201.97 r180 top
C91 "GCM188R71C105KA64D" 0603 1933.5,1034.87 r0 top
"CAUTION HOT SURFACE1" "CAUTION HOT SURFACE" IEC_HotSurface_Small 2223.32,2025.12 r0 top
D2 "SMS3923-040LF" SOD-882 45.81,1106.06 r0 top locked
D3 "SZP6SMB6.8AT3G" SMB 1524.64,696.5 r0 top
DS1 "SML-LX0603SRW-TR" SML-LX0603SRW_SuperRed 119.71,609.17 r90 top
DS2 "SML-LX0603SRW-TR" SML-LX0603SRW_SuperRed 234.35,614.83 r90 top
DS3 "SML-E12Y8WT86" SML-E1_Yellow 15.8,607.06 r270 top
DS4 "SML-E12Y8WT86" SML-E1_Yellow 255.01,402.19 r270 top
DS5 "SML-LX0603SRW-TR" SML-LX0603SRW_SuperRed 33.45,275.58 r90 top
"ESD Susceptible1" "ESD Susceptible" ESD_Overlay_Small 806.3,333.85 r0 top
F1 "0440005.WR" 1206 1360,300 r180 top
FB1 "BLM21PG300SH1D" 0805_HV 1455.18,483.01 r0 top
FB2 "BLM21PG300SH1D" 0805_HV 1455.18,565.13 r0 top
FID1 "Fiducial" Fiducial10-20 225,2200 r90 bottom
FID2 "Fiducial" Fiducial10-20 200,70 r90 bottom
FID3 "Fiducial" Fiducial10-20 2925,2008 r90 bottom
FID4 "Fiducial" Fiducial10-20 2140,80 r90 top
FID5 "Fiducial" Fiducial10-20 2140,80 r90 bottom
FID6 "Fiducial" Fiducial10-20 225.13,2099.98 r90 top
FID7 "Fiducial" Fiducial10-20 200,175 r90 top
J1 "QSH-030-01-L-D-A" Samtec_QSH-030-01-X-D-A 814.05,1886.26 r270 top locked
J2 "128-0711-201" Johnson_128-0711-201 2158.71,293.72 r0 top
J3 "OSTTE030161" On-Shore_OSTTE030161 670.6,-21.34 r0 top
J4 "SSM-103-S-SV" Samtec_SSM-103-x-SV 1727.5,2159.5 r0 bottom
J5 "SSM-110-S-DV" Samtec_SSM-110-x-DV 977.5,409.5 r0 bottom locked
J6 "SSM-110-S-DV" Samtec_SSM-110-x-DV 977.5,2109.5 r0 bottom locked
J7 "SSM-103-S-SV" Samtec_SSM-103-x-SV 1727.5,359.5 r0 bottom
J8 "105017-0001" CONN_105017-0001 1945,-52.27 r180 bottom locked
L1 "DFE252012P-R47M=P2" DFE252012P 1694.05,1366.3 r90 bottom
L2 "DFE252012P-R47M=P2" DFE252012P 1407.85,1376.9 r90 bottom
L3 "DFE252012P-R47M=P2" DFE252012P 1693.55,761.8 r270 bottom
L4 "DFE252012P-R47M=P2" DFE252012P 1401.55,761.8 r270 bottom
L5 "NLCV32T-R10M-EFRD" NLCV32 1677.4,1699.74 r0 bottom
L7 "NLCV32T-R10M-EFRD" NLCV32 2185,845 r90 top
L8 "NLCV32T-R10M-EFRD" NLCV32 1677.4,1817.43 r0 bottom
L9 "NLCV32T-R10M-EFRD" NLCV32 1740.13,1487.07 r0 bottom
LBL1 "Label" Label_650x200 2713.27,681.66 r0 top locked
Logo1 "Texas Instruments" TI_Stacked_Overlay_Small 2640.11,492.24 r0 top
Logo2 "FCC disclaimer" FCC_disclaimer 2273.36,2458.06 r0 top
Logo3 "WEEE logo" WEEE_Minimum 2864.39,277.26 r0 top
LOGO4 "CE Mark" CE_Mark_5mm 2502.7,-21.5 r0 top
P1 "TSW-103-07-T-S" Samtec_TSW-103-07-T-S 31.94,1674.53 r270 top
P2 "TSW-102-07-G-S" TSW-102-07-G-S 612.44,719.75 r90 top
P3 "TSW-102-07-G-S" TSW-102-07-G-S 409,719.42 r90 top
P4 "TSW-102-07-G-S" TSW-102-07-G-S 818.44,718.75 r90 top
P5 "TSW-102-07-G-S" TSW-102-07-G-S 1610,215 r0 top
P6 "PJ-002AH" CUI_PJ-002AH 1180,16.89 r270 top
Q1 "BSS123" SOT-23 120.58,472.75 r90 top
Q2 "BSS123" SOT-23 120.62,472.17 r90 bottom
R1 "CRCW02010000Z0ED" 0201_Silk 730.05,2242.72 r270 top
R2 "CRCW02010000Z0ED" 0201_Silk 930.05,2242.72 r270 top
R3 "CRCW02010000Z0ED" 0201_Silk 1092.38,2242.72 r270 top
R4 "CRCW02010000Z0ED" 0201_Silk 1022.55,2242.72 r270 top
R5 "CRCW02010000Z0ED" 0201_Silk 1054.91,2242.72 r270 top
R6 "CRCW02010000Z0ED" 0201_Silk 1129,2242.72 r270 top
R7 "CRCW02010000Z0ED" 0201_Silk 962.11,1611.72 r270 top
R8 "CRCW02010000Z0ED" 0201_Silk 1329.55,2242.72 r270 top
R9 "CRCW02010000Z0ED" 0201_Silk 829.75,2241.72 r270 top
R10 "CRCW02010000Z0ED" 0201_Silk 1239.25,2241.72 r270 top
R11 "ERJ-2GE0R00X" 0402L 1196.59,1264.15 r0 top
R12 "ERJ-2GE0R00X" 0402L 1015.51,1118 r270 top
R13 "CRCW040210K0FKED" 0402L 1198.4,2234.05 r270 top
R14 "CRCW040210K0FKED" 0402L 638.26,2215.06 r270 top
R15 "CRCW040210K0FKED" 0402L 1042.8,2179.56 r0 top
R16 "CRCW040210K0FKED" 0402L 638.2,2137.15 r90 top
R17 "CRCW02010000Z0ED" 0201_Silk 1060.25,2130.72 r270 top
R18 "CRCW02010000Z0ED" 0201_Silk 1028.21,2130.07 r270 top
R19 "CRCW02010000Z0ED" 0201_Silk 419.25,2129.72 r270 top
R20 "CRCW02010000Z0ED" 0201_Silk 452.11,2129.72 r270 top
R21 "CRCW02010000Z0ED" 0201_Silk 484.35,2129.72 r270 top
R22 "CRCW02010000Z0ED" 0201_Silk 550.11,2129.72 r270 top
R23 "CRCW02010000Z0ED" 0201_Silk 585.61,2129.72 r270 top
R24 "CRCW02010000Z0ED" 0201_Silk 679.75,2129.72 r270 top
R25 "CRCW02010000Z0ED" 0201_Silk 726.25,2129.72 r270 top
R26 "CRCW02010000Z0ED" 0201_Silk 834.11,2129.72 r270 top
R27 "CRCW02010000Z0ED" 0201_Silk 866.61,2129.72 r270 top
R28 "CRCW02010000Z0ED" 0201_Silk 899.11,2129.72 r270 top
R29 "CRCW02010000Z0ED" 0201_Silk 963.83,2129.72 r270 top
R30 "CRCW02010000Z0ED" 0201_Silk 995.75,2129.72 r270 top
R31 "CRCW02010000Z0ED" 0201_Silk 1184,2129.68 r270 top
R32 "CRCW02010000Z0ED" 0201_Silk 1277.55,2129.72 r270 top
R33 "CRCW02010000Z0ED" 0201_Silk 517.39,2129.28 r270 top
R34 "CRCW20100000Z0EF" 2010L 1415.06,2071.26 r0 top
R35 "CRCW02010000Z0ED" 0201_Silk 1326.75,1976.72 r90 top
R36 "CRCW02010000Z0ED" 0201_Silk 1427.25,1976.72 r90 top
R37 "ERJ-2GE0R00X" 0402L 2030.93,2037.7 r180 top
R38 "CRCW040247K5FKED" 0402L 1657.69,2052.34 r180 top
R39 "CRCW020133R2FNED" 0201_Silk 1664.78,1992.45 r0 top
R40 "CRCW020133R2FNED" 0201_Silk 2022.78,1888.35 r0 top
R41 "CRCW040210K0FKED" 0402L 2091.65,1884.48 r0 top
R42 "CRCW020133R2FNED" 0201_Silk 1664.78,1956.85 r0 top
R43 "CRCW040210K0FKED" 0402L 1596.29,1950.4 r180 top
R44 "CRCW020133R2FNED" 0201_Silk 2022.78,1853.85 r0 top
R45 "CRCW020133R2FNED" 0201_Silk 2023.78,1807.35 r0 top
R46 "CRCW040210K0FKED" 0402L 1468.54,1756.11 r180 top
R47 "CRCW040210K0FKED" 0402L 1468.54,1788.74 r0 top
R48 "CRCW02010000Z0ED" 0201_Silk 475.61,1611.72 r270 top
R49 "CRCW02010000Z0ED" 0201_Silk 508.25,1611.72 r270 top
R50 "CRCW02010000Z0ED" 0201_Silk 540.75,1611.72 r270 top
R51 "CRCW02010000Z0ED" 0201_Silk 573.25,1611.72 r270 top
R52 "CRCW02010000Z0ED" 0201_Silk 605.75,1611.72 r270 top
R53 "CRCW02010000Z0ED" 0201_Silk 638.25,1611.72 r270 top
R54 "CRCW02010000Z0ED" 0201_Silk 671.35,1611.72 r270 top
R55 "CRCW02010000Z0ED" 0201_Silk 703.85,1611.72 r270 top
R56 "CRCW02010000Z0ED" 0201_Silk 735.75,1611.72 r270 top
R57 "CRCW02010000Z0ED" 0201_Silk 768.05,1611.72 r270 top
R58 "CRCW02010000Z0ED" 0201_Silk 800.55,1611.72 r270 top
R59 "CRCW02010000Z0ED" 0201_Silk 833.05,1611.72 r270 top
R60 "CRCW02010000Z0ED" 0201_Silk 865.55,1611.72 r270 top
R61 "CRCW02010000Z0ED" 0201_Silk 897.75,1611.72 r270 top
R62 "CRCW02010000Z0ED" 0201_Silk 929.85,1611.72 r270 top
R63 "CRCW02010000Z0ED" 0201_Silk 1161.25,2242.72 r270 top
R64 "CRCW02010000Z0ED" 0201_Silk 1026.61,1611.72 r270 top
R65 "CRCW02010000Z0ED" 0201_Silk 1059.25,1611.72 r270 top
R66 "CRCW02010000Z0ED" 0201_Silk 1091.75,1611.72 r270 top
R67 "CRCW02010000Z0ED" 0201_Silk 1124.25,1611.72 r270 top
R68 "ERJ-2GEJ101X" 0402L 246.04,1553.15 r90 top
R69 "CRCW02010000Z0ED" 0201_Silk 1044.1,1563.62 r180 top
R70 "CRCW02010000Z0ED" 0201_Silk 1091.33,1551.72 r270 top
R71 "CRCW02010000Z0ED" 0201_Silk 1124.33,1551.72 r270 top
R72 "CRCW02010000Z0ED" 0201_Silk 192.5,1461.25 r90 top
R73 "CRCW040210K0FKED" 0402L 192.05,1390.92 r90 top
R74 "CRCW040210K0FKED" 0402L 51.65,1221.14 r180 top
R75 "CRCW02010000Z0ED" 0201_Silk 904.07,1260.47 r90 bottom
R76 "CRCW02010000Z0ED" 0201_Silk 941.93,1260.47 r90 bottom
R77 "ERJ-2GEJ101X" 0402L -27.74,1188.85 r270 top
R78 "ERJ-2GE0R00X" 0402L 1111.7,1088.29 r0 top
R79 "ERJ-2GEJ101X" 0402L 285.35,1098.84 r180 top
R80 "ERJ-2GEJ101X" 0402L -27.26,1087.15 r90 top
R81 "CRCW040210K0FKED" 0402L 1989.89,1085.17 r0 top
R82 "CRCW040212K7FKED" 0402L 2065.31,1085.13 r0 top
R83 "CRCW040210K0FKED" 0402 1927.35,892.02 r0 top
R84 "CRCW040210K0FKED" 0402 1927.35,851.22 r180 top
R85 "CRCW040261R9FKED" 0402L 1142.37,766.8 r90 top
R86 "CRCW040210K0FKED" 0402L 1192.37,766.8 r270 top
R87 "CRCW040261R9FKED" 0402L 1092.37,766.8 r270 top
R88 "CRCW040282K5FKED" 0402L 941.42,759.15 r270 top
R89 "CRCW040210K0FKED" 0402L 981.88,758.85 r270 top
R90 "ERJ-2GEJ361X" 0402L 200.46,737.79 r90 top
R91 "CRCW040210K0FKED" 0402L 149,737.88 r90 top
R92 "CRCW04027K87FKED" 0402L 940.92,681.15 r270 top
R93 "CRCW0402750RFKED" 0402L 981.12,680.36 r270 top
R94 "CRCW02010000Z0ED" 0201_Silk 828.25,532.28 r90 top
R95 "CRCW04027K87FKED" 0402L 648.82,524.55 r90 top
R96 "CRCW040282K5FKED" 0402L 608.78,524.25 r270 top
R97 "ERJ-2GE0R00X" 0402L 285,509.15 r90 top
R98 "CRCW040210K0FKED" 0402L 325.82,508.36 r90 top
R99 "CRCW04027K87FKED" 0402L 409.62,509.15 r90 top
R100 "ERJ-2GEJ511X" 0402L 242.91,509.06 r270 top
R101 "CRCW0402750RFKED" 0402L 366.98,508.85 r90 top
R102 "CRCW02010000Z0ED" 0201_Silk 1230.25,500.28 r90 top
R103 "ERJ-2GEJ511X" 0402L 7.57,500.07 r180 top
R104 "CRCW02010000Z0ED" 0201_Silk 727.75,499.28 r90 top
R105 "CRCW02010000Z0ED" 0201_Silk 929.75,499.28 r90 top
R106 "CRCW02010000Z0ED" 0201_Silk 1030.25,499.28 r90 top
R107 "ERJ-2GE0R00X" 0402L 1129.75,499.28 r90 top
R108 "CRCW02010000Z0ED" 0201_Silk 1330.35,499.08 r90 top
R109 "CRCW02010000Z0ED" 0201_Silk 1362.85,499.08 r90 top
R110 "CRCW0402100KFKED" 0402L 7.72,459.77 r180 top
R111 "CRCW02010000Z0ED" 0201_Silk 2158.86,456.17 r270 top
R112 "CRCW0402750RFKED" 0402L 649.32,447.55 r270 top
R113 "CRCW040210K0FKED" 0402L 608.92,447.55 r90 top
R114 "CRCW040282K5FKED" 0402L 409.52,433.15 r90 top
R115 "CRCW20100000Z0EF" 2010 498.73,431.05 r270 top
R116 "ERJ-2GEJ511X" 0402L 7.78,416.33 r0 top
R117 "ERJ-2GEJ511X" 0402L 308.61,392.15 r90 top
R118 "CRCW20100000Z0EF" 2010 1589.87,377.74 r0 top
R119 "ERJ-2GE0R00X" 0402L 1577.96,1916.14 r270 bottom
R120 "ERJ-2GE0R00X" 0402L 1546.63,1841.79 r270 bottom
R121 "CRCW04023K00FKED" 0402L 1652.02,1893.62 r0 bottom
R122 "CRCW04021K96FKED" 0402L 1732.83,1893.62 r0 bottom
R123 "CRCW04021K00FKED" 0402L 757.28,1632.15 r90 bottom
R124 "CRCW04021K00FKED" 0402L 637.72,1631.85 r270 bottom
R125 "CRCW040210K0FKED" 0402L 1229.27,1234.12 r0 top
R126 "CRCW04021K00FKED" 0402L 717.68,1632.15 r90 bottom
R127 "CRCW04021K00FKED" 0402L 598.12,1631.85 r270 bottom
R128 "ERJ-2GE0R00X" 0402L 246.5,1628.85 r270 bottom
R129 "ERJ-2GE0R00X" 0402L 287,1628.5 r270 bottom
R130 "MCT06030Z0000ZP500" 0603 1390.31,1598.71 r180 bottom
R131 "CRCW04021K96FKED" 0402L 1728.74,1601.78 r0 bottom
R132 "CRCW04023K00FKED" 0402L 1650.78,1566.52 r0 bottom
R133 "MCT06030Z0000ZP500" 0603 1388.69,1529.05 r180 bottom
R134 "CRCW040249R9FKED" 0402L 894.65,1440.6 r0 bottom
R135 "CRCW02010000Z0ED" 0201_Silk 134.78,1366.19 r0 bottom
R136 "CRCW02010000Z0ED" 0201_Silk 134.78,1334.29 r0 bottom
R137 "MCT06030Z0000ZP500" 0603 2628.57,1278.19 r270 bottom
R138 "CRCW0402100KFKED" 0402L 1357.78,1221.96 r270 bottom
R139 "CRCW04021K96FKED" 0402L 1863.35,1207.54 r180 bottom
R140 "CRCW04021K00FKED" 0402L 127.65,1199.52 r0 bottom
R141 "ERJ-2GE0R00X" 0402L 1413.4,1154.01 r180 bottom
R142 "ERJ-2RKF4991X" 0402L 1863.35,1167.04 r180 bottom
R143 "CRCW04024K99FKED" 0402L 1786.35,1166.5 r0 bottom
R144 "CRCW02010000Z0ED" 0201_Silk 1368.78,1066.69 r0 bottom
R145 "CRCW040210K0FKED" 0402L 1833.44,1080.15 r270 bottom
R146 "CRCW02010000Z0ED" 0201_Silk 1368.78,1099.19 r180 bottom
R147 "CRCW04024K99FKED" 0402L 1774,1027.5 r0 bottom
R148 "CRCW040210K0FKED" 0402L 1875,1002.5 r90 bottom
R149 "ERJ-2GEJ102X" 0402L 1916.14,1002.15 r270 bottom
R150 "ERJ-2RKF4991X" 0402L 1833.74,1002.15 r270 bottom
R151 "CRCW0402330KFKED" 0402L 127.65,961.04 r180 bottom
R152 "ERJ-2GE0R00X" 0402L 814,1071.5 r0 top
R153 "CRCW0402330KFKED" 0402L 127.65,917.74 r0 bottom
R154 "ERJ-2GEJ101X" 0402L 736,927.5 r270 top
R155 "CRCW040210K0FKED" 0402L 692.78,861.15 r90 bottom
R156 "CRCW040249K9FKED" 0402L 158.03,739.19 r90 bottom
R157 "CRCW040230K0FKED" 0402L 199.2,738.85 r270 bottom
R158 "CRCW0402100KFKED" 0402L 65.68,589.85 r90 bottom
R159 "ERJ-2GE0R00X" 0402L 24.43,589.71 r90 bottom
R160 "ERJ-2GEJ511X" 0402L 7.7,415.91 r0 bottom
R161 "MCT06030Z0000ZP500" 0603 2060,257.5 r90 bottom
R162 "CRCW02010000Z0ED" 0201_Silk 1470.25,172.28 r90 bottom
R163 "CRCW02010000Z0ED" 0201_Silk 1390.25,171.72 r90 bottom
R164 "CRCW02010000Z0ED" 0201_Silk 1352.75,171.72 r90 bottom
R165 "CRCW02010000Z0ED" 0201_Silk 932.75,169.72 r90 bottom
R166 "CRCW02010000Z0ED" 0201_Silk 832.75,169.28 r90 bottom
R167 "CRCW02010000Z0ED" 0201_Silk 799.13,169.28 r90 bottom
R168 "CRCW02010000Z0ED" 0201_Silk 719.63,169.28 r90 bottom
R169 "CRCW02010000Z0ED" 0201_Silk 685.13,169.28 r90 bottom
R170 "CRCW04022K94FKED" 0402 1428.02,163.85 r270 bottom
R171 "CRCW04022K94FKED" 0402 1315.37,163.85 r270 bottom
R172 "CRCW0402100KFKED" 0402L 870.18,161.15 r90 bottom
R173 "CRCW0402100KFKED" 0402L 759.88,161.15 r90 bottom
R174 "CRCW040230K0FKED" 0402L 2212.4,-18.11 r90 bottom
R175 "MCT06030Z0000ZP500" 0603 1671,60.5 r90 bottom
R176 "MCT06030Z0000ZP500" 0603 -4,743.5 r270 top
R177 "ERJ-2GE0R00X" 0402L 1209.5,676.57 r270 top
R178 "CRCW040210K0FKED" 0402L 1246.5,806.17 r270 top
R179 "CRCW040210K0FKED" 0402L 1562.35,1009.92 r180 top
R180 "CRCW02010000Z0ED" 0201_Silk 1569.78,1048.33 r0 top
R181 "CRCW02010000Z0ED" 0201_Silk 1732.22,991.17 r0 top
R182 "CRCW02010000Z0ED" 0201_Silk 1684.67,1095.78 r90 top
R183 "ERJ-2GE0R00X" 0402L 1739.65,1026.68 r0 top
R184 "CRCW040210K0FKED" 0402L 140.38,1013.35 r270 top
R185 "CRCW02010000Z0ED" 0201_Silk 257.83,1021.22 r90 top
R186 "CRCW02010000Z0ED" 0201_Silk 271.78,973.33 r0 top
R187 "ERJ-2GE0R00X" 0402L 200.98,913.35 r270 top
R188 "CRCW02010000Z0ED" 0201_Silk 163.83,921.22 r90 top
R189 "ERJ-2GEJ361X" 0402L -14.4,266.73 r90 top
R190 "CRCW04023R83FKED" 0402L 1403.85,1273.74 r90 bottom
R191 "CRCW04023R83FKED" 0402L 1734.8,1267.65 r90 bottom
R192 "CRCW04023R83FKED" 0402L 1364.9,867.35 r270 bottom
R193 "CRCW04023R83FKED" 0402L 1735.6,865.35 r270 bottom
R194 "CRCW04024K87FKED" 0402L 677.52,1631.85 r270 bottom
R195 "CRCW040210K0FKED" 0402L 1216.27,1169.81 r0 top
R196 "CRCW040210K0FKED" 0402L 971,1725.91 r270 bottom
R197 "CRCW02010000Z0ED" 0201 2568,1959 r180 top
R198 "CRCW02010000Z0ED" 0201 2568,1922 r180 top
S1 "CHS-01TB" SW_CHS-01TB 760,1230 r90 top locked
SW1 "KMR243GLFG" SW_KMR243GLFG 336.65,1437.52 r180 top
SW2 "KMR243GLFG" SW_KMR243GLFG 335.35,1209.76 r180 top
TP1 "TSW-101-17-T-S" Samtec_TSW-101-17-T-S 195,1840 r0 top
TP2 "TSW-101-17-T-S" Samtec_TSW-101-17-T-S 196.94,1739.77 r0 top
U1 "MX25V1635FZNQ" WSON-8L_6x5MM_EP 1845.23,1980.68 r0 top
U2 "AWR1243FBIGABLQ1" ABL0161A 2294.55,1477.9 r180 top locked
U3 "TCAN1042HGVDQ1" D0008A_L 1117.37,940.26 r270 top
U4 "TPS7A8101QDRBRQ1" DRB0008A 2048.18,912.92 r270 top
U5 "TPS7A8801RTJR" RTJ0020D 1599.35,1728.32 r0 top
U6 "TM4C1294NCPDTT3" PDT0128A 511.79,1248.04 r0 bottom
U7 "LM4040C25QDBZR" DBZ0003A_N 8.08,1177.09 r180 bottom
U8 "LP87524JRNFRQ1" RNF0026C 1551,1080.5 r0 bottom locked
U9 "TPS79601DRBR" DRB0008B 62.83,736.32 r270 bottom
U10 "TPD4E004DRYR" DRY0006A 1976,355.5 r270 top
U11 "TMP112AIDRLR" DRL0006A 1651.46,1024.75 r0 top
U12 "TMP112AIDRLR" DRL0006A 200.81,1001.54 r270 top
U13 "TS3A5018RSVR" RSV0016A 1091.86,1207.21 r270 top
Y1 "CX3225SA40000D0PTWCC" Kyocera_CX3225SA 1978.72,1281.14 r180 top
Y2 "NX3225SA-16.000M-STD-CRS-2" NDK_NX3225SA 978.31,1081.5 r270 bottom
ZZ1 "This Assembly Note is for PCB labels only" AssemblyNoteLabel -484.07,3129.33 r0 top
ZZ2 "These assemblies are ESD sensitive, ESD precautions shall be observed." AssemblyNote -484.07,3020.44 r0 top
ZZ3 "These assemblies must be clean and free from flux and all contaminants. Use of no clean flux is not acceptable." AssemblyNote -484.07,2931.89 r0 top
ZZ4 "These assemblies must comply with workmanship standards IPC-A-610 Class 2, unless otherwise specified." AssemblyNote -484.07,2843.33 r0 top
ZZ5 "Micro USB cable, Brackets, Screws, Nuts, Jumpers and Bump on need to be placed in a plastic bag" AssemblyNote -485.07,2750.33 r0 top

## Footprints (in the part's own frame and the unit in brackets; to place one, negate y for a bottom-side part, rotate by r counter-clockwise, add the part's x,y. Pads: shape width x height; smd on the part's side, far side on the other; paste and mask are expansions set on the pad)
0201 [mm] "Data from Kemet datasheet CC101_COM dated 7/28/11"
  rect 0.46x0.42 smd: 1(-0.33,0) 2(0.33,0)
0201_033 [mm] "SMD, 2-Leads, Height 0.33mm"
  rect 0.46x0.42 smd: 1(-0.33,0) 2(0.33,0)
0201_Silk [mm] "Data from Kemet datasheet CC101_COM dated 7/28/11"
  rect 0.46x0.42 smd: 1(-0.33,0) 2(0.33,0)
  silkscreen extent -0.75,-0.4 0.75,0.4
0402 [mm] "0402 from SM-752 data"
  rect 0.8x0.6 smd: 1(-0.6,0) 2(0.6,0)
  silkscreen extent -1.22,-0.52 1.22,0.52
0402_065L [mm] "0402"
  rect 0.6x0.5 smd: 1(-0.5,0) 2(0.5,0)
0402L [mm] "0402 from SM-752 data"
  rect 0.6x0.5 smd: 1(-0.5,0) 2(0.5,0)
0603 [mm] "0603 from SM-752 data"
  rect 1x0.95 smd: 1(-0.8,0) 2(0.8,0)
  silkscreen extent -1.52,-0.69 1.52,0.69
0805 [mm] "0805 from SM-752 data"
  rect 1.3x1.5 smd: 1(-0.85,0) 2(0.85,0)
  silkscreen extent -1.72,-0.97 1.72,0.97
0805_HV [mil] "0805 with 30mil clearance between pads"
  rect 50x63 smd: 1(-40,0) 2(40,0)
  silkscreen extent -74,-40 74,40
0805_HV1 [mm] "Custom footprint based on analyzing multiple manufacturer recommendations"
  rrect10% 1x1.25 smd: 1(-1,0) 2(1,0)
  silkscreen extent -0.2,-0.75 0.2,0.75
1206 [mm] "1206 from SM-752 data"
  rect 1.3x1.85 smd: 1(-1.45,0) 2(1.45,0)
  silkscreen extent -2.4,-1.21 2.4,1.21
1206_180 [mm] "1206_180"
  rect 1.1x1.6 smd: 1(-1.7,0) 2(1.7,0)
  silkscreen extent -0.9,-1 0.9,1
2010 [mm] "Chip Capacitor, Body 5.08x2.54mm, IPC Medium Density"
  rect 1.6x2.7 smd: 1(-2.3,0) 2(2.3,0)
  silkscreen extent -3.42,-1.65 3.42,1.65
2010L [mm]
  rect 1.2x2.7 smd: 1(-2.2,0) 2(2.2,0)
  silkscreen extent -1.2,-1.25 1.2,1.25
3528-21 [mm] "Medium Density IPC, based on Kemet datasheet 2016-10-20"
  rrect6% 1.8x2.23 smd: 1(-1.46,0) 2(1.46,0)
  silkscreen extent -2.29,-1.5 0.76,1.5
